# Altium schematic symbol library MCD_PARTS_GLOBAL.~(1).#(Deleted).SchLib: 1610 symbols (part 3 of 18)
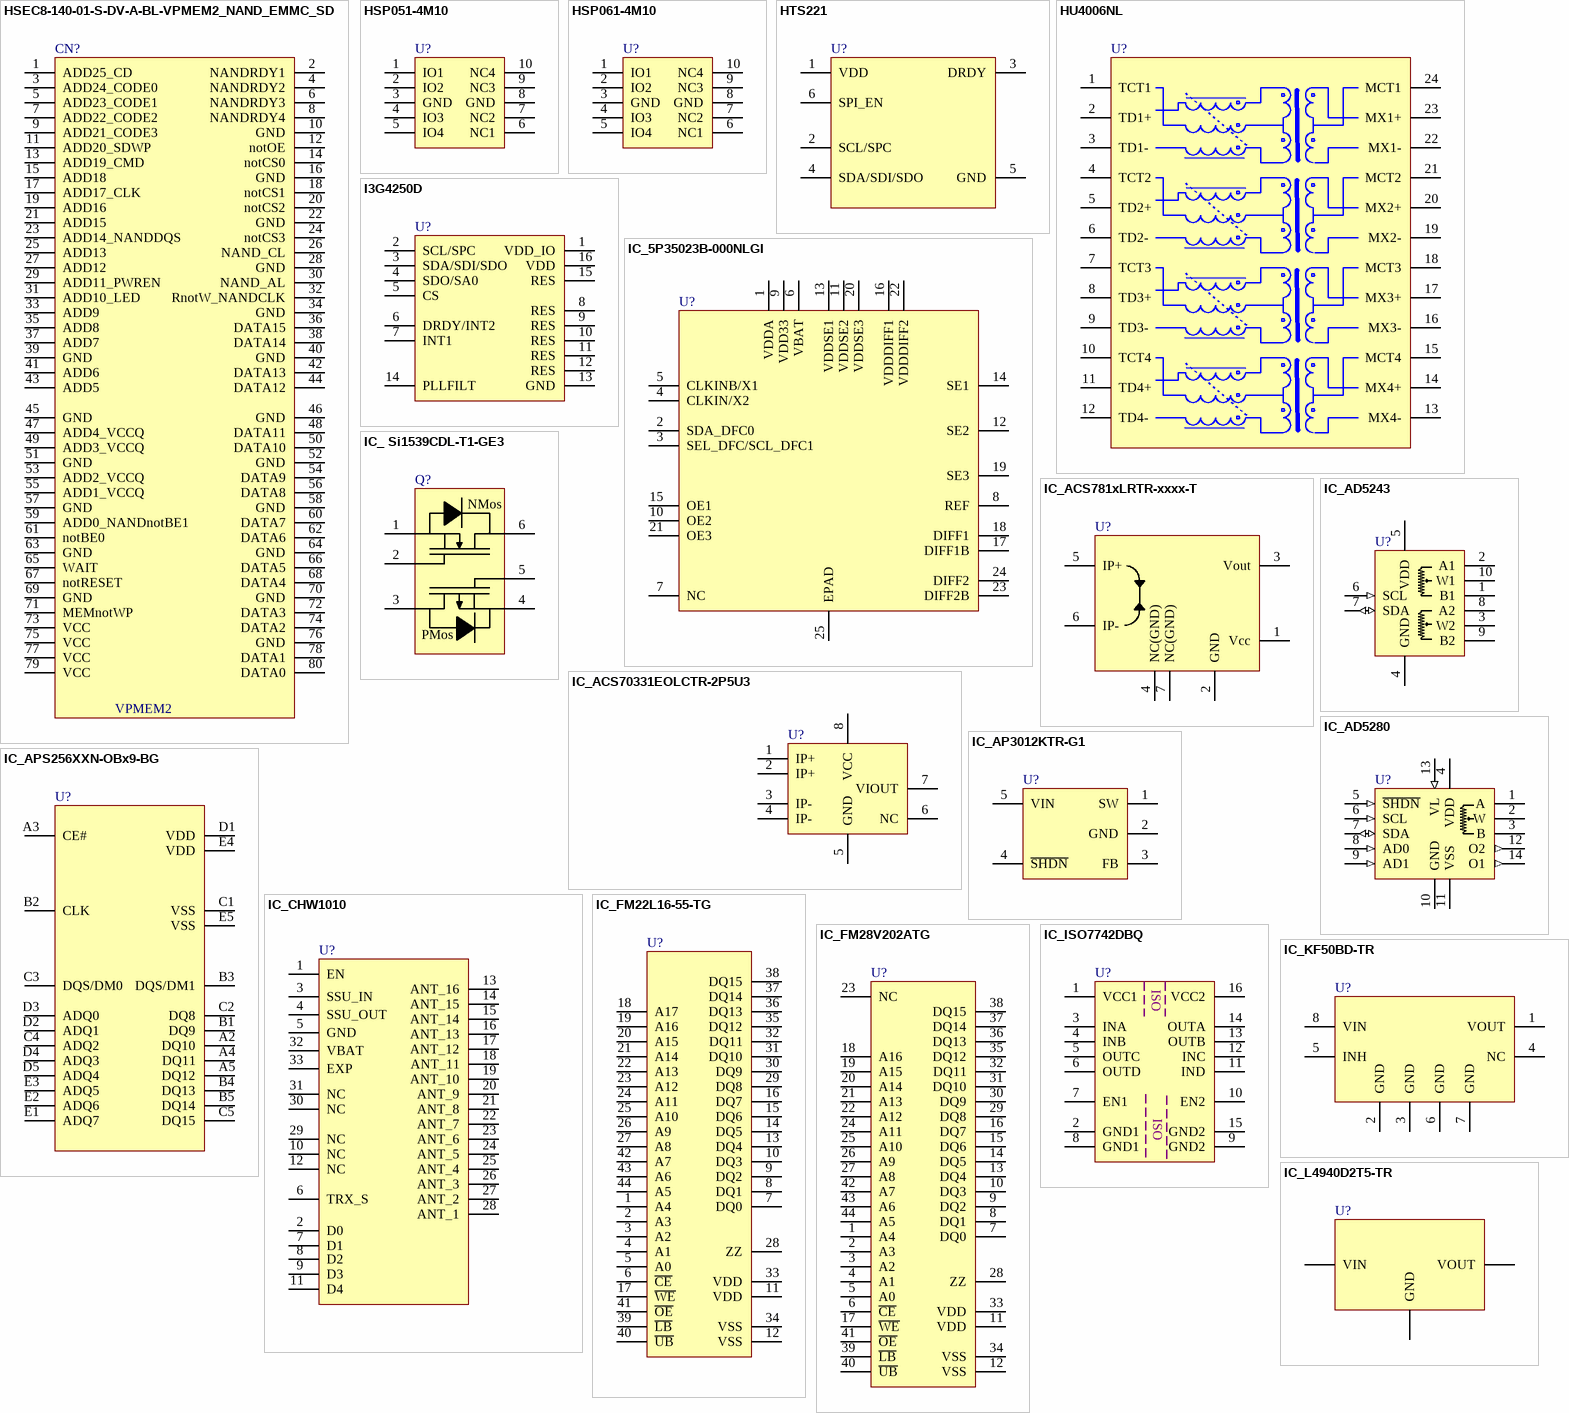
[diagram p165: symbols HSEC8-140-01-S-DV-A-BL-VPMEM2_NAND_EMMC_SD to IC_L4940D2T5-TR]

## HSEC8-140-01-S-DV-A-BL-VPMEM2_NAND_EMMC_SD
designator CN?
pins: 1 ADD25_CD, 2 NANDRDY1, 3 ADD24_CODE0, 4 NANDRDY2, 5 ADD23_CODE1, 6 NANDRDY3, 7 ADD22_CODE2, 8 NANDRDY4, 9 ADD21_CODE3, 10 GND, 11 ADD20_SDWP, 12 notOE, 13 ADD19_CMD, 14 notCS0, 15 ADD18, 16 GND, 17 ADD17_CLK, 18 notCS1, 19 ADD16, 20 notCS2, 21 ADD15, 22 GND, 23 ADD14_NANDDQS, 24 notCS3, 25 ADD13, 26 NAND_CL, 27 ADD12, 28 GND, 29 ADD11_PWREN, 30 NAND_AL, 31 ADD10_LED, 32 RnotW_NANDCLK, 33 ADD9, 34 GND, 35 ADD8, 36 DATA15, 37 ADD7, 38 DATA14, 39 GND, 40 GND, 41 ADD6, 42 DATA13, 43 ADD5, 44 DATA12, 45 GND, 46 GND, 47 ADD4_VCCQ, 48 DATA11, 49 ADD3_VCCQ, 50 DATA10, 51 GND, 52 GND, 53 ADD2_VCCQ, 54 DATA9, 55 ADD1_VCCQ, 56 DATA8, 57 GND, 58 GND, 59 ADD0_NANDnotBE1, 60 DATA7, 61 notBE0, 62 DATA6, 63 GND, 64 GND, 65 WAIT, 66 DATA5, 67 notRESET, 68 DATA4, 69 GND, 70 GND, 71 MEMnotWP, 72 DATA3, 73 VCC, 74 DATA2, 75 VCC, 76 GND, 77 VCC, 78 DATA1, 79 VCC, 80 DATA0

## HSP051-4M10
designator U?
pins: 1 IO1, 2 IO2, 3 GND, 4 IO3, 5 IO4, 6 NC1, 7 NC2, 8 GND, 9 NC3, 10 NC4

## HSP061-4M10
designator U?
pins: 1 IO1, 2 IO2, 3 GND, 4 IO3, 5 IO4, 6 NC1, 7 NC2, 8 GND, 9 NC3, 10 NC4

## HTS221
designator U?
pins: 1 VDD, 2 SCL/SPC, 3 DRDY, 4 SDA/SDI/SDO, 5 GND, 6 SPI_EN

## HU4006NL
designator U?
pins: 1 TCT1, 2 TD1+, 3 TD1-, 4 TCT2, 5 TD2+, 6 TD2-, 7 TCT3, 8 TD3+, 9 TD3-, 10 TCT4, 11 TD4+, 12 TD4-, 13 MX4-, 14 MX4+, 15 MCT4, 16 MX3-, 17 MX3+, 18 MCT3, 19 MX2-, 20 MX2+, 21 MCT2, 22 MX1-, 23 MX1+, 24 MCT1

## I3G4250D
designator U?
pins: 1 VDD_IO, 2 SCL/SPC, 3 SDA/SDI/SDO, 4 SDO/SA0, 5 CS, 6 DRDY/INT2, 7 INT1, 8 RES, 9 RES, 10 RES, 11 RES, 12 RES, 13 GND, 14 PLLFILT, 15 RES, 16 VDD

## IC_5P35023B-000NLGI
designator U?
pins: 1 VDDA, 2 SDA_DFC0, 3 SEL_DFC/SCL_DFC1, 4 CLKIN/X2, 5 CLKINB/X1, 6 VBAT, 7 NC, 8 REF, 9 VDD33, 10 OE2, 11 VDDSE2, 12 SE2, 13 VDDSE1, 14 SE1, 15 OE1, 16 VDDDIFF1, 17 DIFF1B, 18 DIFF1, 19 SE3, 20 VDDSE3, 21 OE3, 22 VDDDIFF2, 23 DIFF2B, 24 DIFF2, 25 EPAD

## IC_ Si1539CDL-T1-GE3
designator Q?
pins: 1 S1, 2 G1, 3 D2, 4 S2, 5 G2, 6 D1

## IC_ACS781xLRTR-xxxx-T
designator U?
pins: 1 Vcc, 2 GND, 3 Vout, 4 NC(GND), 5 IP+, 6 IP-, 7 NC(GND)

## IC_ACS70331EOLCTR-2P5U3
designator U?
pins: 1 IP+, 2 IP+, 3 IP-, 4 IP-, 5 GND, 6 NC, 7 VIOUT, 8 VCC

## IC_AD5243
designator U?
pins: 1 B1, 2 A1, 3 W2, 4 GND, 5 VDD, 6 SCL (in), 7 SDA (io), 8 A2, 9 B2, 10 W1

## IC_AD5280
designator U?
pins: 1 A, 2 W, 3 B, 4 VDD, 5 ~{SHDN} (in), 6 SCL (in), 7 SDA (io), 8 AD0 (in), 9 AD1 (in), 10 GND, 11 VSS, 12 O2 (out), 13 VL (in), 14 O1 (out)

## IC_AP3012KTR-G1
designator U?
pins: 1 SW, 2 GND, 3 FB, 4 ~{SHDN}, 5 VIN

## IC_APS256XXN-OBx9-BG
designator U?
pins: A2 DQ10, A3 CE#, A4 DQ11, A5 DQ12, B1 DQ9, B2 CLK, B3 DQS/DM1, B4 DQ13, B5 DQ14, C1 VSS, C2 DQ8, C3 DQS/DM0, C4 ADQ2, C5 DQ15, D1 VDD, D2 ADQ1, D3 ADQ0, D4 ADQ3, D5 ADQ4, E1 ADQ7, E2 ADQ6, E3 ADQ5, E4 VDD, E5 VSS

## IC_CHW1010
designator U?
pins: 1 EN "CHIP ENABLE", 2 D0 "DIGITAL CONTROL INPUT", 3 SSU_IN "SOFT-SWITCHING RAMP MODULATOR INPUT", 4 SSU_OUT "SOFT-SWITCHING RAMP MODULATOR OUTPUT", 5 GND (power), 6 TRX_S "TRX IN/OUT IN CASE OF SINGLE-END ANTENNA INTERFACE", 7 D1 "DIGITAL CONTROL INPUT", 8 D2 "DIGITAL CONTROL INPUT", 9 D3 "DIGITAL CONTROL INPUT", 10 NC, 11 D4 "DIGITAL CONTROL INPUT", 12 NC, 13 ANT_16 "ANTENNA FEED-PORT 16", 14 ANT_15 "ANTENNA FEED-PORT 15", 15 ANT_14 "ANTENNA FEED-PORT 14", 16 ANT_13 "ANTENNA FEED-PORT 16", 17 ANT_12 "ANTENNA FEED-PORT 12", 18 ANT_11 "ANTENNA FEED-PORT 11", 19 ANT_10 "ANTENNA FEED-PORT 10", 20 ANT_9 "ANTENNA FEED-PORT 9", 21 ANT_8 "ANTENNA FEED-PORT 8", 22 ANT_7 "ANTENNA FEED-PORT 7", 23 ANT_6 "ANTENNA FEED-PORT 6", 24 ANT_5 "ANTENNA FEED-PORT 5", 25 ANT_4 "ANTENNA FEED-PORT 4", 26 ANT_3 "ANTENNA FEED-PORT 3", 27 ANT_2 "ANTENNA FEED-PORT 2", 28 ANT_1 "ANTENNA FEED-PORT 1", 29 NC, 30 NC, 31 NC, 32 VBAT (power) "BATTERY VOLTAGE", 33 EXP (power) "GND"

## IC_FM22L16-55-TG
designator U?
pins: 1 A4, 2 A3, 3 A2, 4 A1, 5 A0, 6 ~{CE}, 7 DQ0, 8 DQ1, 9 DQ2, 10 DQ3, 11 VDD, 12 VSS, 13 DQ4, 14 DQ5, 15 DQ6, 16 DQ7, 17 ~{WE}, 18 A17, 19 A16, 20 A15, 21 A14, 22 A13, 23 A12, 24 A11, 25 A10, 26 A9, 27 A8, 28 ZZ, 29 DQ8, 30 DQ9, 31 DQ10, 32 DQ11, 33 VDD, 34 VSS, 35 DQ12, 36 DQ13, 37 DQ14, 38 DQ15, 39 ~{LB}, 40 ~{UB}, 41 ~{OE}, 42 A7, 43 A6, 44 A5

## IC_FM28V202ATG
designator U?
pins: 1 A4, 2 A3, 3 A2, 4 A1, 5 A0, 6 ~{CE}, 7 DQ0, 8 DQ1, 9 DQ2, 10 DQ3, 11 VDD, 12 VSS, 13 DQ4, 14 DQ5, 15 DQ6, 16 DQ7, 17 ~{WE}, 18 A16, 19 A15, 20 A14, 21 A13, 22 A12, 23 NC, 24 A11, 25 A10, 26 A9, 27 A8, 28 ZZ, 29 DQ8, 30 DQ9, 31 DQ10, 32 DQ11, 33 VDD, 34 VSS, 35 DQ12, 36 DQ13, 37 DQ14, 38 DQ15, 39 ~{LB}, 40 ~{UB}, 41 ~{OE}, 42 A7, 43 A6, 44 A5

## IC_ISO7742DBQ
designator U?
pins: 1 VCC1 (power), 2 GND1 (power), 3 INA, 4 INB, 5 OUTC, 6 OUTD, 7 EN1, 8 GND1 (power), 9 GND2 (power), 10 EN2, 11 IND, 12 INC, 13 OUTB, 14 OUTA, 15 GND2 (power), 16 VCC2 (power)

## IC_KF50BD-TR
designator U?
pins: 1 VOUT, 2 GND, 3 GND, 4 NC, 5 INH, 6 GND, 7 GND, 8 VIN

## IC_L4940D2T5-TR
designator U?
pins: 1 VIN (power), 2 GND (power), 3 VOUT (power)

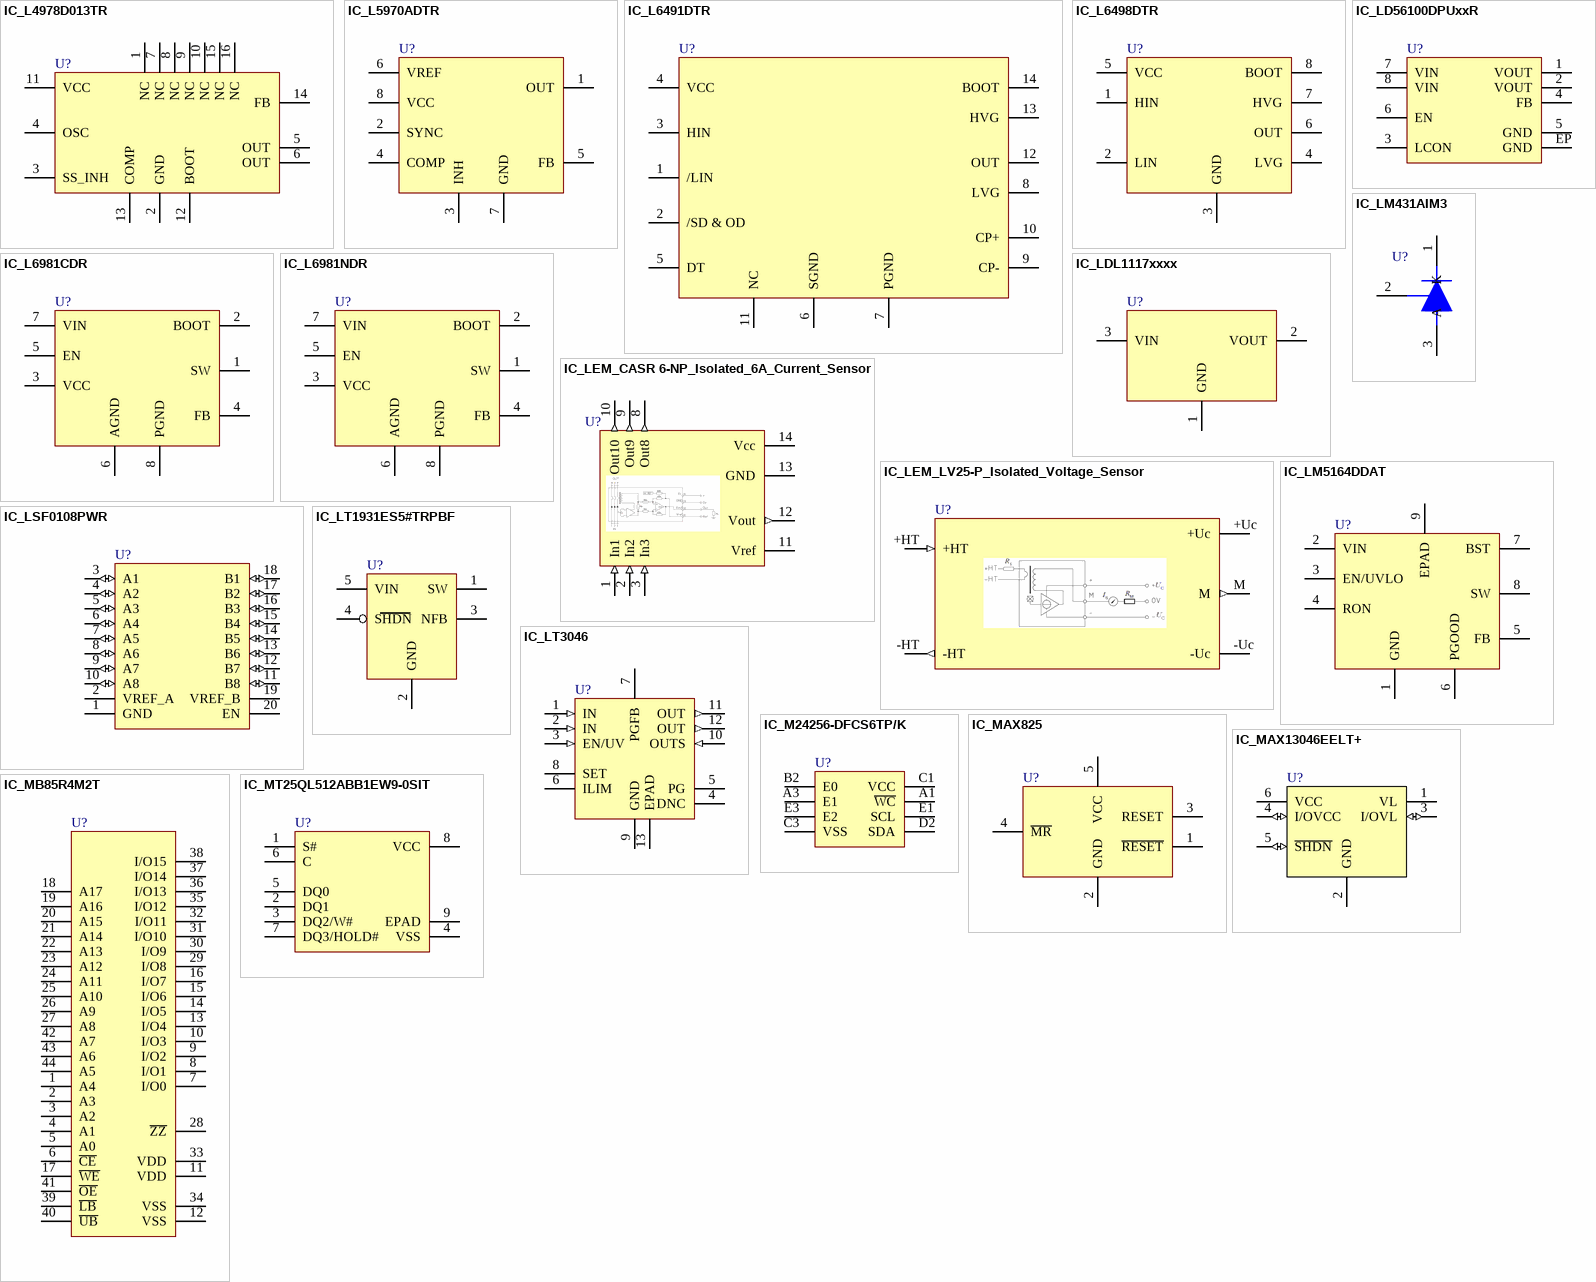
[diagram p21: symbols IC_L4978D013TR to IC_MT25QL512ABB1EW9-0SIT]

## IC_L4978D013TR
designator U?
pins: 1 NC, 2 GND (power), 3 SS_INH, 4 OSC, 5 OUT, 6 OUT, 7 NC, 8 NC, 9 NC, 10 NC, 11 VCC (power), 12 BOOT, 13 COMP, 14 FB, 15 NC, 16 NC

## IC_L5970ADTR
designator U?
pins: 1 OUT, 2 SYNC, 3 INH, 4 COMP, 5 FB, 6 VREF, 7 GND, 8 VCC (power)

## IC_L6491DTR
designator U?
pins: 1 /LIN, 2 /SD & OD, 3 HIN, 4 VCC (power), 5 DT, 6 SGND, 7 PGND, 8 LVG, 9 CP-, 10 CP+, 11 NC, 12 OUT, 13 HVG, 14 BOOT

## IC_L6498DTR
designator U?
pins: 1 HIN, 2 LIN, 3 GND, 4 LVG, 5 VCC (power), 6 OUT, 7 HVG, 8 BOOT

## IC_L6981CDR
designator U?
pins: 1 SW, 2 BOOT, 3 VCC, 4 FB, 5 EN (power), 6 AGND, 7 VIN, 8 PGND

## IC_L6981NDR
designator U?
pins: 1 SW, 2 BOOT, 3 VCC, 4 FB, 5 EN (power), 6 AGND, 7 VIN, 8 PGND

## IC_LD56100DPUxxR
designator U?
pins: 1 VOUT, 2 VOUT, 3 LCON, 4 FB, 5 GND, 6 EN, 7 VIN, 8 VIN, EP GND

## IC_LDL1117xxxx
designator U?
pins: 1 GND, 2 VOUT, 3 VIN

## IC_LEM_CASR 6-NP_Isolated_6A_Current_Sensor
designator U?
pins: 1 In1 (in), 2 In2 (in), 3 In3 (in), 8 Out8 (out), 9 Out9 (out), 10 Out10 (out), 11 Vref (power), 12 Vout (out), 13 GND (power), 14 Vcc (power)

## IC_LEM_LV25-P_Isolated_Voltage_Sensor
designator U?
pins: +HT (in), +Uc (power), -HT (out), -Uc (power), M (out)

## IC_LM431AIM3
designator U?
pins: 1 K, 2 Ref, 3 A

## IC_LM5164DDAT
designator U?
pins: 1 GND, 2 VIN, 3 EN/UVLO (power), 4 RON, 5 FB, 6 PGOOD, 7 BST, 8 SW, 9 EPAD

## IC_LSF0108PWR
designator U?
pins: 1 GND (power), 2 VREF_A (power), 3 A1 (io), 4 A2 (io), 5 A3 (io), 6 A4 (io), 7 A5 (io), 8 A6 (io), 9 A7 (io), 10 A8 (io), 11 B8 (io), 12 B7 (io), 13 B6 (io), 14 B5 (io), 15 B4 (io), 16 B3 (io), 17 B2 (io), 18 B1 (io), 19 VREF_B (power), 20 EN (power)

## IC_LT1931ES5#TRPBF
designator U?
pins: 1 SW, 2 GND, 3 NFB, 4 SHDN (power), 5 VIN

## IC_LT3046
designator U?
pins: 1 IN (in), 2 IN (in), 3 EN/UV (in), 4 DNC, 5 PG (oc), 6 ILIM, 7 PGFB, 8 SET, 9 GND, 10 OUTS (in), 11 OUT (out), 12 OUT (out), 13 EPAD

## IC_M24256-DFCS6TP/K
designator U?
pins: A1 ~{WC}, A3 E1, B2 E0, C1 VCC, C3 VSS, D2 SDA, E1 SCL, E3 E2

## IC_MAX825
designator U?
pins: 1 ~{RESET}, 2 GND, 3 RESET, 4 ~{MR}, 5 VCC

## IC_MAX13046EELT+
designator U?
pins: 1 VL (power), 2 GND (power), 3 I/OVL (io), 4 I/OVCC (io), 5 ~{SHDN} (io), 6 VCC (power)

## IC_MB85R4M2T
designator U?
pins: 1 A4, 2 A3, 3 A2, 4 A1, 5 A0, 6 ~{CE}, 7 I/O0, 8 I/O1, 9 I/O2, 10 I/O3, 11 VDD, 12 VSS, 13 I/O4, 14 I/O5, 15 I/O6, 16 I/O7, 17 ~{WE}, 18 A17, 19 A16, 20 A15, 21 A14, 22 A13, 23 A12, 24 A11, 25 A10, 26 A9, 27 A8, 28 ~{ZZ}, 29 I/O8, 30 I/O9, 31 I/O10, 32 I/O11, 33 VDD, 34 VSS, 35 I/O12, 36 I/O13, 37 I/O14, 38 I/O15, 39 ~{LB}, 40 ~{UB}, 41 ~{OE}, 42 A7, 43 A6, 44 A5

## IC_MT25QL512ABB1EW9-0SIT
designator U?
pins: 1 S#, 2 DQ1, 3 DQ2/W#, 4 VSS, 5 DQ0, 6 C, 7 DQ3/HOLD#, 8 VCC, 9 EPAD

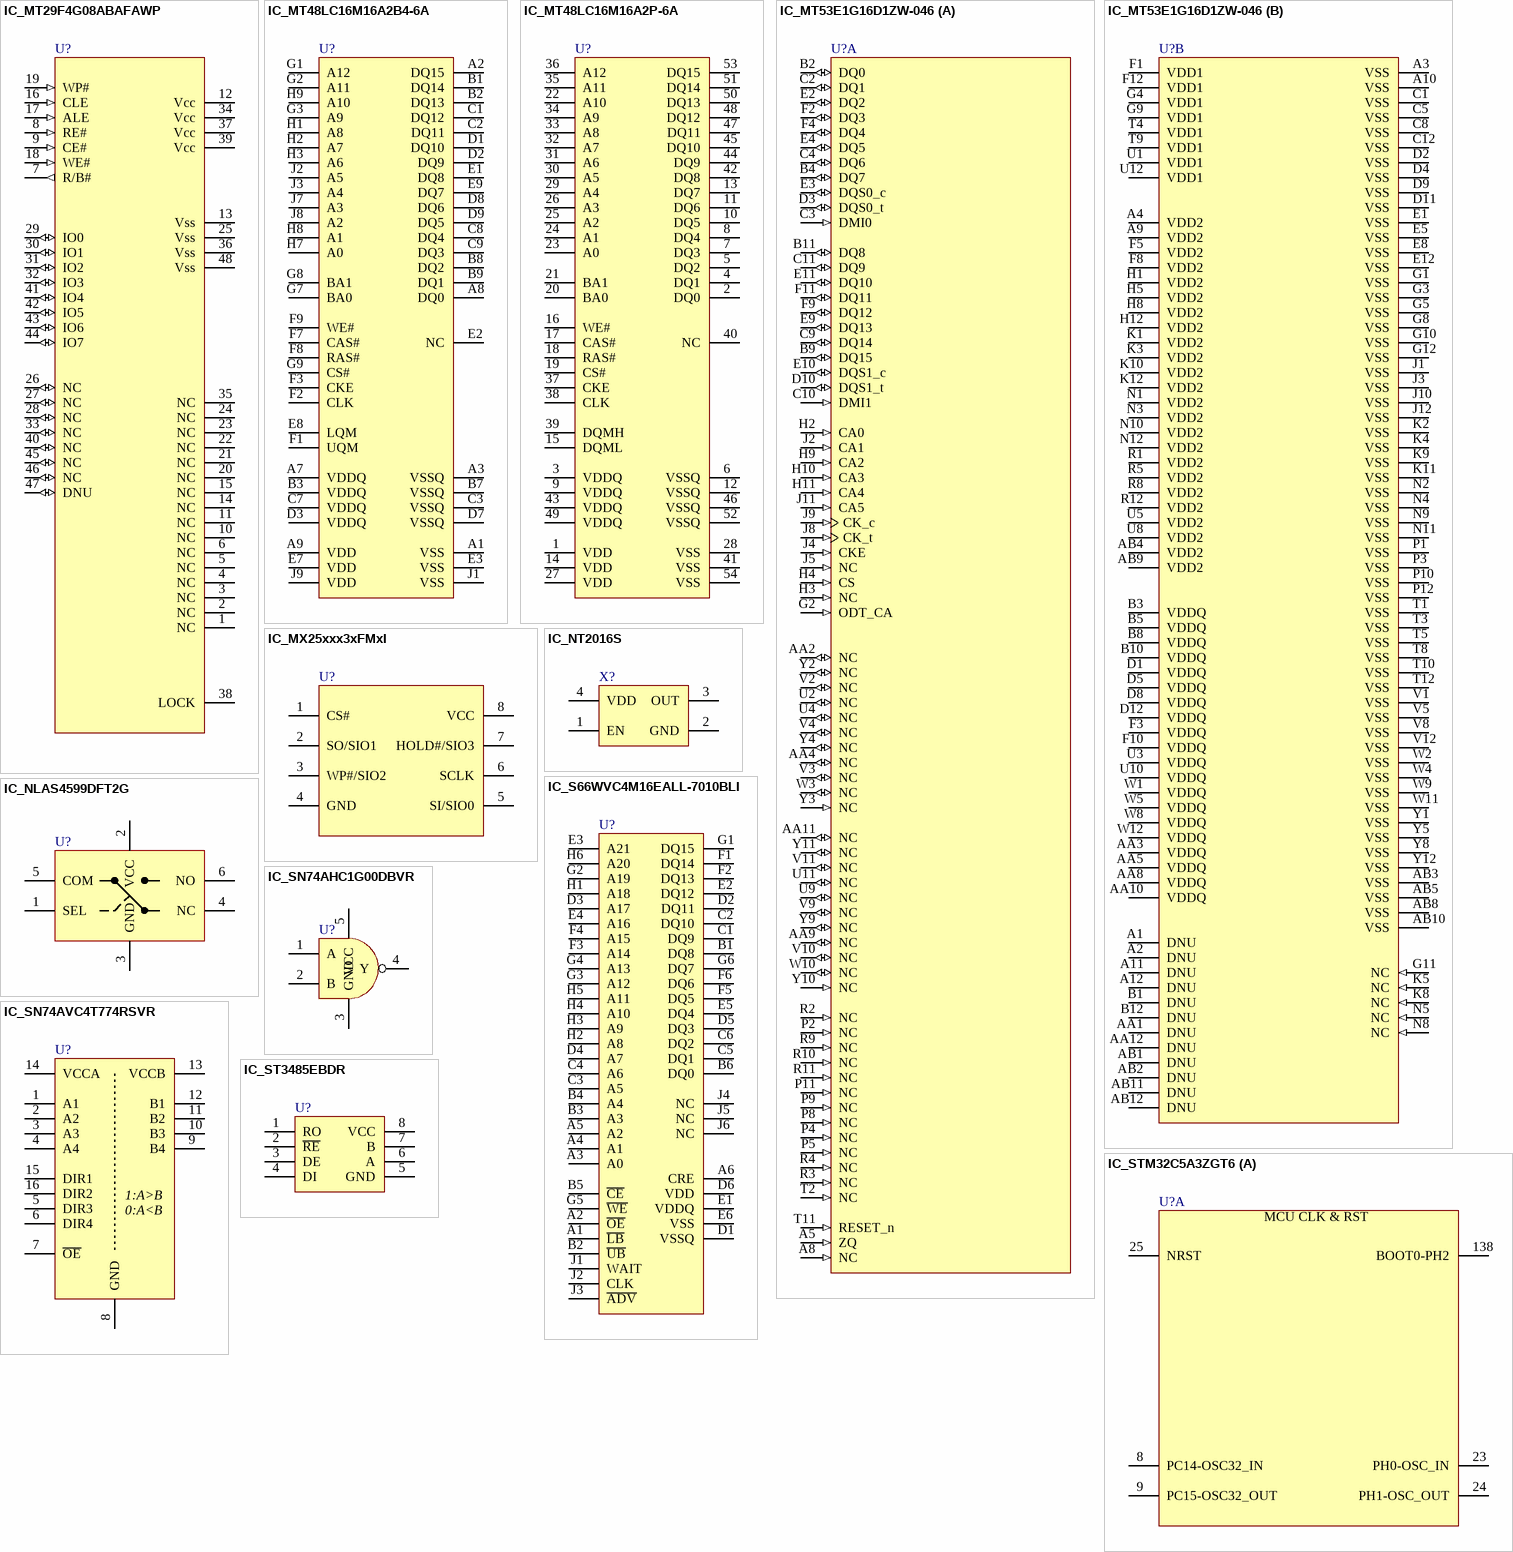
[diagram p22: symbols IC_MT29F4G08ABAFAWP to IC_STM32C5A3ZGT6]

## IC_MT29F4G08ABAFAWP
designator U?
pins: 1 NC, 2 NC, 3 NC, 4 NC, 5 NC, 6 NC, 7 R/B# (out), 8 RE# (in), 9 CE# (in), 10 NC, 11 NC, 12 Vcc (power), 13 Vss (power), 14 NC, 15 NC, 16 CLE (in), 17 ALE (in), 18 WE# (in), 19 WP# (in), 20 NC, 21 NC, 22 NC, 23 NC, 24 NC, 25 Vss (power), 26 NC (io), 27 NC (io), 28 NC (io), 29 IO0 (io), 30 IO1 (io), 31 IO2 (io), 32 IO3 (io), 33 NC (io), 34 Vcc (power), 35 NC, 36 Vss (power), 37 Vcc (power), 38 LOCK, 39 Vcc (power), 40 NC (io), 41 IO4 (io), 42 IO5 (io), 43 IO6 (io), 44 IO7 (io), 45 NC (io), 46 NC (io), 47 DNU (io), 48 Vss (power)

## IC_MT48LC16M16A2B4-6A
designator U?
pins: A1 VSS, A2 DQ15, A3 VSSQ, A7 VDDQ, A8 DQ0, A9 VDD, B1 DQ14, B2 DQ13, B3 VDDQ, B7 VSSQ, B8 DQ2, B9 DQ1, C1 DQ12, C2 DQ11, C3 VSSQ, C7 VDDQ, C8 DQ4, C9 DQ3, D1 DQ10, D2 DQ9, D3 VDDQ, D7 VSSQ, D8 DQ6, D9 DQ5, E1 DQ8, E2 NC, E3 VSS, E7 VDD, E8 LQM, E9 DQ7, F1 UQM, F2 CLK, F3 CKE, F7 CAS#, F8 RAS#, F9 WE#, G1 A12, G2 A11, G3 A9, G7 BA0, G8 BA1, G9 CS#, H1 A8, H2 A7, H3 A6, H7 A0, H8 A1, H9 A10, J1 VSS, J2 A5, J3 A4, J7 A3, J8 A2, J9 VDD

## IC_MT48LC16M16A2P-6A
designator U?
pins: 1 VDD, 2 DQ0, 3 VDDQ, 4 DQ1, 5 DQ2, 6 VSSQ, 7 DQ3, 8 DQ4, 9 VDDQ, 10 DQ5, 11 DQ6, 12 VSSQ, 13 DQ7, 14 VDD, 15 DQML, 16 WE#, 17 CAS#, 18 RAS#, 19 CS#, 20 BA0, 21 BA1, 22 A10, 23 A0, 24 A1, 25 A2, 26 A3, 27 VDD, 28 VSS, 29 A4, 30 A5, 31 A6, 32 A7, 33 A8, 34 A9, 35 A11, 36 A12, 37 CKE, 38 CLK, 39 DQMH, 40 NC, 41 VSS, 42 DQ8, 43 VDDQ, 44 DQ9, 45 DQ10, 46 VSSQ, 47 DQ11, 48 DQ12, 49 VDDQ, 50 DQ13, 51 DQ14, 52 VSSQ, 53 DQ15, 54 VSS

## IC_MT53E1G16D1ZW-046
designator U?
part A pins: A5 ZQ (in) "External impedance (240 ohm): This signal is used to calibrate the device output impedance.", A8 NC (in), AA2 NC (io) "Data input/output: Bidirectional data bus.", AA4 NC (io) "Data input/output: Bidirectional data bus.", AA9 NC (io) "Data input/output: Bidirectional data bus.", AA11 NC (io) "Data input/output: Bidirectional data bus.", B2 DQ0 (io) "Data input/output: Bidirectional data bus.", B4 DQ7 (io) "Data input/output: Bidirectional data bus.", B9 DQ15 (io) "Data input/output: Bidirectional data bus.", B11 DQ8 (io) "Data input/output: Bidirectional data bus.", C2 DQ1 (io) "Data input/output: Bidirectional data bus.", C3 DMI0 (in) "Input data mask: DM is an input mask signal for write data. Although DM ballsare input-only, the DM loading is designed to match that of DQ and DQS balls.DM[3:0] is DM for each of the four data bytes, respectively.", C4 DQ6 (io) "Data input/output: Bidirectional data bus.", C9 DQ14 (io) "Data input/output: Bidirectional data bus.", C10 DMI1 (in) "Input data mask: DM is an input mask signal for write data. Although DM ballsare input-only, the DM loading is designed to match that of DQ and DQS balls.DM[3:0] is DM for each of the four data bytes, respectively.", C11 DQ9 (io) "Data input/output: Bidirectional data bus.", D3 DQS0_t (io) "Data strobe: The data strobe is bidirectional (used for read and write data) andcomplementary (DQS and DQS#). It is edge-aligned output with read data andcentered input with write data. DQS[3:0]/DQS[3:0]# is DQS for each of (See Datasheet)", D10 DQS1_t (io) "Data strobe: The data strobe is bidirectional (used for read and write data) andcomplementary (DQS and DQS#). It is edge-aligned output with read data andcentered input with write data. DQS[3:0]/DQS[3:0]# is DQS for each of (See Datasheet)", E2 DQ2 (io) "Data input/output: Bidirectional data bus.", E3 DQS0_c (io) "Data strobe: The data strobe is bidirectional (used for read and write data) andcomplementary (DQS and DQS#). It is edge-aligned output with read data andcentered input with write data. DQS[3:0]/DQS[3:0]# is DQS for each of (See Datasheet)", E4 DQ5 (io) "Data input/output: Bidirectional data bus.", E9 DQ13 (io) "Data input/output: Bidirectional data bus.", E10 DQS1_c (io) "Data strobe: The data strobe is bidirectional (used for read and write data) andcomplementary (DQS and DQS#). It is edge-aligned output with read data andcentered input with write data. DQS[3:0]/DQS[3:0]# is DQS for each of (See Datasheet)", E11 DQ10 (io) "Data input/output: Bidirectional data bus.", F2 DQ3 (io) "Data input/output: Bidirectional data bus.", F4 DQ4 (io) "Data input/output: Bidirectional data bus.", F9 DQ12 (io) "Data input/output: Bidirectional data bus.", F11 DQ11 (io) "Data input/output: Bidirectional data bus.", G2 ODT_CA (in) "on die termination on CA", H2 CA0 (in) "Command/address inputs: Provide the command and address inputs accordingto the command truth table.", H3 NC (in), H4 CS (in) "Chip select: CS# is considered part of the command code and is sampled at therising edge of CK.", H9 CA2 (in) "Command/address inputs: Provide the command and address inputs accordingto the command truth table.", H10 CA3 (in) "Command/address inputs: Provide the command and address inputs accordingto the command truth table.", H11 CA4 (in) "Command/address inputs: Provide the command and address inputs accordingto the command truth table.", J2 CA1 (in) "Command/address inputs: Provide the command and address inputs accordingto the command truth table.", J4 CKE (in) "Clock enable: CKE HIGH activates and CKE LOW deactivates the internal clocksignals, input buffers, and output drivers. Power-saving modes are entered andexited via CKE transitions. CKE is considered part of the command code. (See Datasheet)", J5 NC (in), J8 CK_t (in) "Clock: CK and CK# are differential clock inputs. All CA inputs are sampled onboth rising and falling edges of CK. CS and CKE inputs are sampled at the risingedge of CK. AC timings are referenced to clock.", J9 CK_c (in) "Clock: CK and CK# are differential clock inputs. All CA inputs are sampled onboth rising and falling edges of CK. CS and CKE inputs are sampled at the risingedge of CK. AC timings are referenced to clock.", J11 CA5 (in) "Command/address inputs: Provide the command and address inputs accordingto the command truth table.", P2 NC (in) "Command/address inputs: Provide the command and address inputs accordingto the command truth table.", P4 NC (in) "Clock enable: CKE HIGH activates and CKE LOW deactivates the internal clocksignals, input buffers, and output drivers. Power-saving modes are entered andexited via CKE transitions. CKE is considered part of the command code. (See Datasheet)", P5 NC (in), P8 NC (in) "Clock: CK and CK# are differential clock inputs. All CA inputs are sampled onboth rising and falling edges of CK. CS and CKE inputs are sampled at the risingedge of CK. AC timings are referenced to clock.", P9 NC (in) "Clock: CK and CK# are differential clock inputs. All CA inputs are sampled onboth rising and falling edges of CK. CS and CKE inputs are sampled at the risingedge of CK. AC timings are referenced to clock.", P11 NC (in) "Command/address inputs: Provide the command and address inputs accordingto the command truth table.", R2 NC (in) "Command/address inputs: Provide the command and address inputs accordingto the command truth table.", R3 NC (in), R4 NC (in) "Chip select: CS# is considered part of the command code and is sampled at therising edge of CK.", R9 NC (in) "Command/address inputs: Provide the command and address inputs accordingto the command truth table.", R10 NC (in) "Command/address inputs: Provide the command and address inputs accordingto the command truth table.", R11 NC (in) "Command/address inputs: Provide the command and address inputs accordingto the command truth table.", T2 NC (in) "on die termination on CA", T11 RESET_n (in) "Reset active low", U2 NC (io) "Data input/output: Bidirectional data bus.", U4 NC (io) "Data input/output: Bidirectional data bus.", U9 NC (io) "Data input/output: Bidirectional data bus.", U11 NC (io) "Data input/output: Bidirectional data bus.", V2 NC (io) "Data input/output: Bidirectional data bus.", V3 NC (io) "Data strobe: The data strobe is bidirectional (used for read and write data) andcomplementary (DQS and DQS#). It is edge-aligned output with read data andcentered input with write data. DQS[3:0]/DQS[3:0]# is DQS for each of (See Datasheet)", V4 NC (io) "Data input/output: Bidirectional data bus.", V9 NC (io) "Data input/output: Bidirectional data bus.", V10 NC (io) "Data strobe: The data strobe is bidirectional (used for read and write data) andcomplementary (DQS and DQS#). It is edge-aligned output with read data andcentered input with write data. DQS[3:0]/DQS[3:0]# is DQS for each of (See Datasheet)", V11 NC (io) "Data input/output: Bidirectional data bus.", W3 NC (io) "Data strobe: The data strobe is bidirectional (used for read and write data) andcomplementary (DQS and DQS#). It is edge-aligned output with read data andcentered input with write data. DQS[3:0]/DQS[3:0]# is DQS for each of (See Datasheet)", W10 NC (io) "Data strobe: The data strobe is bidirectional (used for read and write data) andcomplementary (DQS and DQS#). It is edge-aligned output with read data andcentered input with write data. DQS[3:0]/DQS[3:0]# is DQS for each of (See Datasheet)", Y2 NC (io) "Data input/output: Bidirectional data bus.", Y3 NC (in) "Input data mask: DM is an input mask signal for write data. Although DM ballsare input-only, the DM loading is designed to match that of DQ and DQS balls.DM[3:0] is DM for each of the four data bytes, respectively.", Y4 NC (io) "Data input/output: Bidirectional data bus.", Y9 NC (io) "Data input/output: Bidirectional data bus.", Y10 NC (in) "Input data mask: DM is an input mask signal for write data. Although DM ballsare input-only, the DM loading is designed to match that of DQ and DQS balls.DM[3:0] is DM for each of the four data bytes, respectively.", Y11 NC (io) "Data input/output: Bidirectional data bus."
part B pins: A1 DNU "Do not use: Must be grounded or left floating.", A2 DNU "Do not use: Must be grounded or left floating.", A3 VSS (power) "Common ground.", A4 VDD2 (power) "Core power: Supply 2.", A9 VDD2 (power) "Core power: Supply 2.", A10 VSS (power) "Common ground.", A11 DNU "Do not use: Must be grounded or left floating.", A12 DNU "Do not use: Must be grounded or left floating.", AA1 DNU "Do not use: Must be grounded or left floating.", AA3 VDDQ (power) "DQ power supply: Isolated on the die for improved noise immunity.", AA5 VDDQ (power) "DQ power supply: Isolated on the die for improved noise immunity.", AA8 VDDQ (power) "DQ power supply: Isolated on the die for improved noise immunity.", AA10 VDDQ (power) "DQ power supply: Isolated on the die for improved noise immunity.", AA12 DNU "Do not use: Must be grounded or left floating.", AB1 DNU "Do not use: Must be grounded or left floating.", AB2 DNU "Do not use: Must be grounded or left floating.", AB3 VSS "Common ground.", AB4 VDD2 (power) "Core power: Supply 2.", AB5 VSS "Common ground.", AB8 VSS "Common ground.", AB9 VDD2 (power) "Core power: Supply 2.", AB10 VSS "Common ground.", AB11 DNU "Do not use: Must be grounded or left floating.", AB12 DNU "Do not use: Must be grounded or left floating.", B1 DNU "Do not use: Must be grounded or left floating.", B3 VDDQ (power) "DQ power supply: Isolated on the die for improved noise immunity.", B5 VDDQ (power) "DQ power supply: Isolated on the die for improved noise immunity.", B8 VDDQ (power) "DQ power supply: Isolated on the die for improved noise immunity.", B10 VDDQ (power) "DQ power supply: Isolated on the die for improved noise immunity.", B12 DNU "Do not use: Must be grounded or left floating.", C1 VSS (power) "Common ground.", C5 VSS (power) "Common ground.", C8 VSS (power) "Common ground.", C12 VSS (power) "Common ground.", D1 VDDQ (power) "DQ power supply: Isolated on the die for improved noise immunity.", D2 VSS (power) "Common ground.", D4 VSS (power) "Common ground.", D5 VDDQ (power) "DQ power supply: Isolated on the die for improved noise immunity.", D8 VDDQ (power) "DQ power supply: Isolated on the die for improved noise immunity.", D9 VSS (power) "Common ground.", D11 VSS (power) "Common ground.", D12 VDDQ (power) "DQ power supply: Isolated on the die for improved noise immunity.", E1 VSS (power) "Common ground.", E5 VSS (power) "Common ground.", E8 VSS (power) "Common ground.", E12 VSS (power) "Common ground.", F1 VDD1 (power) "Core power: Supply 1.", F3 VDDQ (power) "DQ power supply: Isolated on the die for improved noise immunity.", F5 VDD2 (power) "Core power: Supply 2.", F8 VDD2 (power) "Core power: Supply 2.", F10 VDDQ (power) "DQ power supply: Isolated on the die for improved noise immunity.", F12 VDD1 (power) "Core power: Supply 1.", G1 VSS (power) "Common ground.", G3 VSS (power) "Common ground.", G4 VDD1 (power) "Core power: Supply 1.", G5 VSS (power) "Common ground.", G8 VSS (power) "Common ground.", G9 VDD1 (power) "Core power: Supply 1.", G10 VSS (power) "Common ground.", G11 NC (in) "Not connected", G12 VSS (power) "Common ground.", H1 VDD2 (power) "Core power: Supply 2.", H5 VDD2 (power) "Core power: Supply 2.", H8 VDD2 (power) "Core power: Supply 2.", H12 VDD2 (power) "Core power: Supply 2.", J1 VSS (power) "Common ground.", J3 VSS (power) "Common ground.", J10 VSS (power) "Common ground.", J12 VSS (power) "Common ground.", K1 VDD2 (power) "Core power: Supply 2.", K2 VSS (power) "Common ground.", K3 VDD2 (power) "Core power: Supply 2.", K4 VSS (power) "Common ground.", K5 NC (in) "Not connected", K8 NC (in) "Not connected", K9 VSS (power) "Common ground.", K10 VDD2 (power) "Core power: Supply 2.", K11 VSS "Common ground.", K12 VDD2 (power) "Core power: Supply 2.", N1 VDD2 (power) "Core power: Supply 2.", N2 VSS "Common ground.", N3 VDD2 (power) "Core power: Supply 2.", N4 VSS "Common ground.", N5 NC (in) "Not connected", N8 NC (in) "Not connected", N9 VSS "Common ground.", N10 VDD2 (power) "Core power: Supply 2.", N11 VSS "Common ground.", N12 VDD2 (power) "Core power: Supply 2.", P1 VSS "Common ground.", P3 VSS (power) "Common ground.", P10 VSS (power) "Common ground.", P12 VSS "Common ground.", R1 VDD2 (power) "Core power: Supply 2.", R5 VDD2 (power) "Core power: Supply 2.", R8 VDD2 (power) "Core power: Supply 2.", R12 VDD2 (power) "Core power: Supply 2.", T1 VSS "Common ground.", T3 VSS "Common ground.", T4 VDD1 (power) "Core power: Supply 1.", T5 VSS "Common ground.", T8 VSS "Common ground.", T9 VDD1 (power) "Core power: Supply 1.", T10 VSS "Common ground.", T12 VSS "Common ground.", U1 VDD1 (power) "Core power: Supply 1.", U3 VDDQ (power) "DQ power supply: Isolated on the die for improved noise immunity.", U5 VDD2 (power) "Core power: Supply 2.", U8 VDD2 (power) "Core power: Supply 2.", U10 VDDQ (power) "DQ power supply: Isolated on the die for improved noise immunity.", U12 VDD1 (power) "Core power: Supply 1.", V1 VSS (power) "Common ground.", V5 VSS (power) "Common ground.", V8 VSS "Common ground.", V12 VSS "Common ground.", W1 VDDQ (power) "DQ power supply: Isolated on the die for improved noise immunity.", W2 VSS "Common ground.", W4 VSS "Common ground.", W5 VDDQ (power) "DQ power supply: Isolated on the die for improved noise immunity.", W8 VDDQ (power) "DQ power supply: Isolated on the die for improved noise immunity.", W9 VSS "Common ground.", W11 VSS "Common ground.", W12 VDDQ (power) "DQ power supply: Isolated on the die for improved noise immunity.", Y1 VSS "Common ground.", Y5 VSS "Common ground.", Y8 VSS "Common ground.", Y12 VSS "Common ground."

## IC_MX25xxx3xFMxI
designator U?
pins: 1 CS#, 2 SO/SIO1, 3 WP#/SIO2, 4 GND, 5 SI/SIO0, 6 SCLK, 7 HOLD#/SIO3, 8 VCC

## IC_NLAS4599DFT2G
designator U?
pins: 1 SEL, 2 VCC, 3 GND, 4 NC, 5 COM, 6 NO

## IC_NT2016S
designator X?
pins: 1 EN, 2 GND, 3 OUT, 4 VDD

## IC_S66WVC4M16EALL-7010BLI
designator U?
pins: A1 ~{LB}, A2 ~{OE}, A3 A0, A4 A1, A5 A2, A6 CRE, B1 DQ8, B2 ~{UB}, B3 A3, B4 A4, B5 ~{CE}, B6 DQ0, C1 DQ9, C2 DQ10, C3 A5, C4 A6, C5 DQ1, C6 DQ2, D1 VSSQ, D2 DQ11, D3 A17, D4 A7, D5 DQ3, D6 VDD, E1 VDDQ, E2 DQ12, E3 A21, E4 A16, E5 DQ4, E6 VSS, F1 DQ14, F2 DQ13, F3 A14, F4 A15, F5 DQ5, F6 DQ6, G1 DQ15, G2 A19, G3 A12, G4 A13, G5 ~{WE}, G6 DQ7, H1 A18, H2 A8, H3 A9, H4 A10, H5 A11, H6 A20, J1 WAIT, J2 CLK, J3 ~{ADV}, J4 NC, J5 NC, J6 NC

## IC_SN74AHC1G00DBVR
designator U?
pins: 1 NC hidden, 1 A, 2 B, 3 GND, 4 Y, 5 VCC

## IC_SN74AVC4T774RSVR
designator U?
pins: 1 A1, 2 A2, 3 A3, 4 A4, 5 DIR3, 6 DIR4, 7 ~{OE}, 8 GND, 9 B4, 10 B3, 11 B2, 12 B1, 13 VCCB, 14 VCCA, 15 DIR1, 16 DIR2

## IC_ST3485EBDR
designator U?
pins: 1 RO, 2 ~{RE}, 3 DE, 4 DI, 5 GND, 6 A, 7 B, 8 VCC

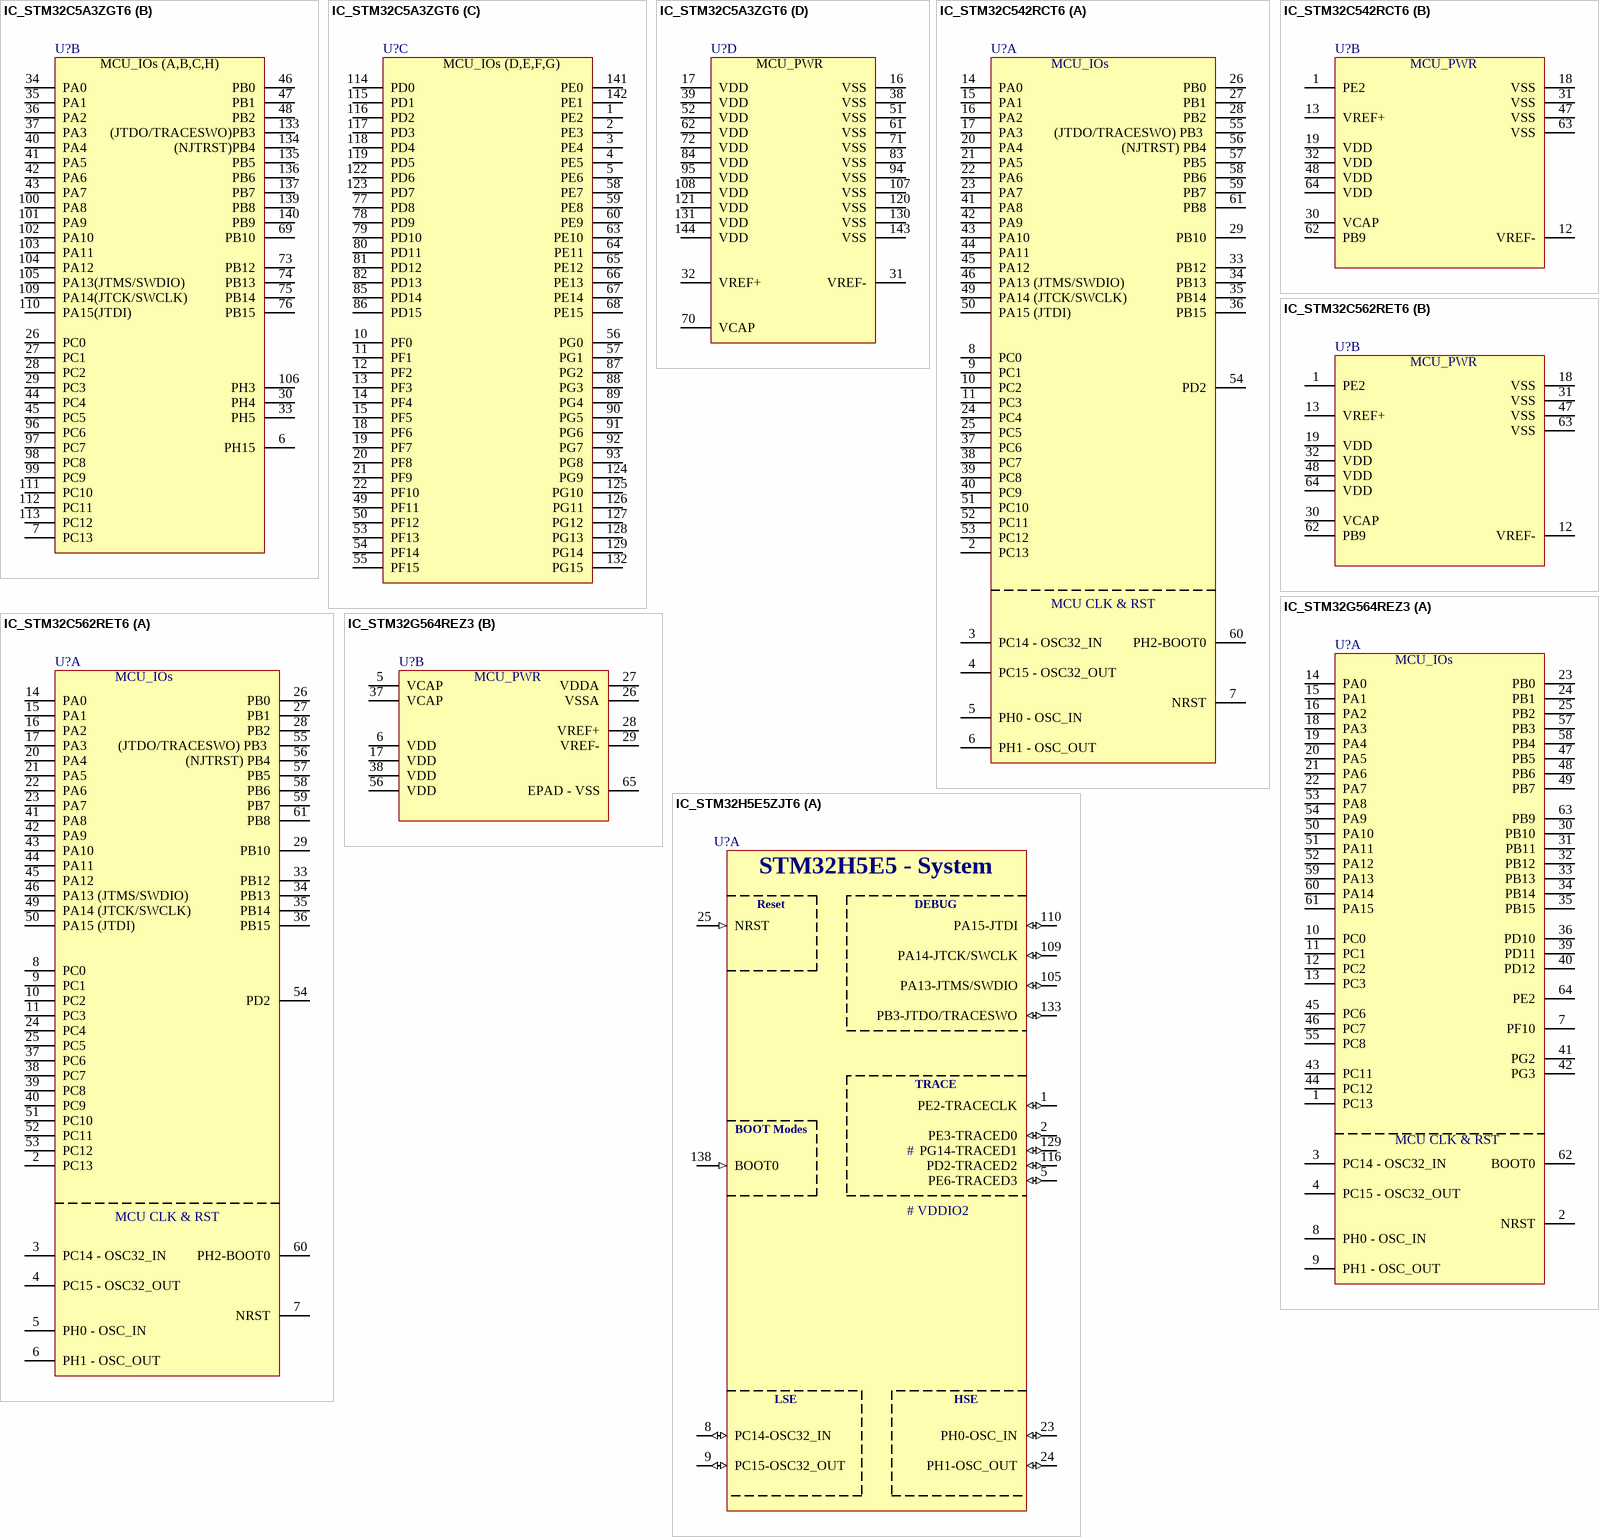
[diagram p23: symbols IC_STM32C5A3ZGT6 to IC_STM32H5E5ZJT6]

## IC_STM32C5A3ZGT6
designator U?
part A pins: 8 PC14-OSC32_IN, 9 PC15-OSC32_OUT, 23 PH0-OSC_IN, 24 PH1-OSC_OUT, 25 NRST, 138 BOOT0-PH2
part B pins: 6 PH15, 7 PC13, 26 PC0, 27 PC1, 28 PC2, 29 PC3, 30 PH4, 33 PH5, 34 PA0, 35 PA1, 36 PA2, 37 PA3, 40 PA4, 41 PA5, 42 PA6, 43 PA7, 44 PC4, 45 PC5, 46 PB0, 47 PB1, 48 PB2, 69 PB10, 73 PB12, 74 PB13, 75 PB14, 76 PB15, 96 PC6, 97 PC7, 98 PC8, 99 PC9, 100 PA8, 101 PA9, 102 PA10, 103 PA11, 104 PA12, 105 PA13(JTMS/SWDIO), 106 PH3, 109 PA14(JTCK/SWCLK), 110 PA15(JTDI), 111 PC10, 112 PC11, 113 PC12, 133 (JTDO/TRACESWO)PB3, 134 (NJTRST)PB4, 135 PB5, 136 PB6, 137 PB7, 139 PB8, 140 PB9
part C pins: 1 PE2, 2 PE3, 3 PE4, 4 PE5, 5 PE6, 10 PF0, 11 PF1, 12 PF2, 13 PF3, 14 PF4, 15 PF5, 18 PF6, 19 PF7, 20 PF8, 21 PF9, 22 PF10, 49 PF11, 50 PF12, 53 PF13, 54 PF14, 55 PF15, 56 PG0, 57 PG1, 58 PE7, 59 PE8, 60 PE9, 63 PE10, 64 PE11, 65 PE12, 66 PE13, 67 PE14, 68 PE15, 77 PD8, 78 PD9, 79 PD10, 80 PD11, 81 PD12, 82 PD13, 85 PD14, 86 PD15, 87 PG2, 88 PG3, 89 PG4, 90 PG5, 91 PG6, 92 PG7, 93 PG8, 114 PD0, 115 PD1, 116 PD2, 117 PD3, 118 PD4, 119 PD5, 122 PD6, 123 PD7, 124 PG9, 125 PG10, 126 PG11, 127 PG12, 128 PG13, 129 PG14, 132 PG15, 141 PE0, 142 PE1
part D pins: 16 VSS, 17 VDD, 31 VREF-, 32 VREF+, 38 VSS, 39 VDD, 51 VSS, 52 VDD, 61 VSS, 62 VDD, 70 VCAP, 71 VSS, 72 VDD, 83 VSS, 84 VDD, 94 VSS, 95 VDD, 107 VSS, 108 VDD, 120 VSS, 121 VDD, 130 VSS, 131 VDD, 143 VSS, 144 VDD

## IC_STM32C542RCT6
designator U?
part A pins: 2 PC13, 3 PC14 - OSC32_IN, 4 PC15 - OSC32_OUT, 5 PH0 - OSC_IN, 6 PH1 - OSC_OUT, 7 NRST, 8 PC0, 9 PC1, 10 PC2, 11 PC3, 14 PA0, 15 PA1, 16 PA2, 17 PA3, 20 PA4, 21 PA5, 22 PA6, 23 PA7, 24 PC4, 25 PC5, 26 PB0, 27 PB1, 28 PB2, 29 PB10, 33 PB12, 34 PB13, 35 PB14, 36 PB15, 37 PC6, 38 PC7, 39 PC8, 40 PC9, 41 PA8, 42 PA9, 43 PA10, 44 PA11, 45 PA12, 46 PA13 (JTMS/SWDIO), 49 PA14 (JTCK/SWCLK), 50 PA15 (JTDI), 51 PC10, 52 PC11, 53 PC12, 54 PD2, 55 (JTDO/TRACESWO) PB3 , 56 (NJTRST) PB4, 57 PB5, 58 PB6, 59 PB7, 60 PH2-BOOT0, 61 PB8
part B pins: 1 PE2, 12 VREF-, 13 VREF+, 18 VSS, 19 VDD, 30 VCAP, 31 VSS, 32 VDD, 47 VSS, 48 VDD, 62 PB9, 63 VSS, 64 VDD

## IC_STM32C562RET6
designator U?
part A pins: 2 PC13, 3 PC14 - OSC32_IN, 4 PC15 - OSC32_OUT, 5 PH0 - OSC_IN, 6 PH1 - OSC_OUT, 7 NRST, 8 PC0, 9 PC1, 10 PC2, 11 PC3, 14 PA0, 15 PA1, 16 PA2, 17 PA3, 20 PA4, 21 PA5, 22 PA6, 23 PA7, 24 PC4, 25 PC5, 26 PB0, 27 PB1, 28 PB2, 29 PB10, 33 PB12, 34 PB13, 35 PB14, 36 PB15, 37 PC6, 38 PC7, 39 PC8, 40 PC9, 41 PA8, 42 PA9, 43 PA10, 44 PA11, 45 PA12, 46 PA13 (JTMS/SWDIO), 49 PA14 (JTCK/SWCLK), 50 PA15 (JTDI), 51 PC10, 52 PC11, 53 PC12, 54 PD2, 55 (JTDO/TRACESWO) PB3 , 56 (NJTRST) PB4, 57 PB5, 58 PB6, 59 PB7, 60 PH2-BOOT0, 61 PB8
part B pins: 1 PE2, 12 VREF-, 13 VREF+, 18 VSS, 19 VDD, 30 VCAP, 31 VSS, 32 VDD, 47 VSS, 48 VDD, 62 PB9, 63 VSS, 64 VDD

## IC_STM32G564REZ3
designator U?
part A pins: 1 PC13, 2 NRST, 3 PC14 - OSC32_IN, 4 PC15 - OSC32_OUT, 7 PF10, 8 PH0 - OSC_IN, 9 PH1 - OSC_OUT, 10 PC0, 11 PC1, 12 PC2, 13 PC3, 14 PA0, 15 PA1, 16 PA2, 18 PA3, 19 PA4, 20 PA5, 21 PA6, 22 PA7, 23 PB0, 24 PB1, 25 PB2, 30 PB10, 31 PB11, 32 PB12, 33 PB13, 34 PB14, 35 PB15, 36 PD10, 39 PD11, 40 PD12, 41 PG2, 42 PG3, 43 PC11, 44 PC12, 45 PC6, 46 PC7, 47 PB5, 48 PB6, 49 PB7, 50 PA10, 51 PA11, 52 PA12, 53 PA8, 54 PA9, 55 PC8, 57 PB3, 58 PB4, 59 PA13, 60 PA14, 61 PA15, 62 BOOT0, 63 PB9, 64 PE2
part B pins: 5 VCAP, 6 VDD, 17 VDD, 26 VSSA, 27 VDDA, 28 VREF+, 29 VREF-, 37 VCAP, 38 VDD, 56 VDD, 65 EPAD - VSS

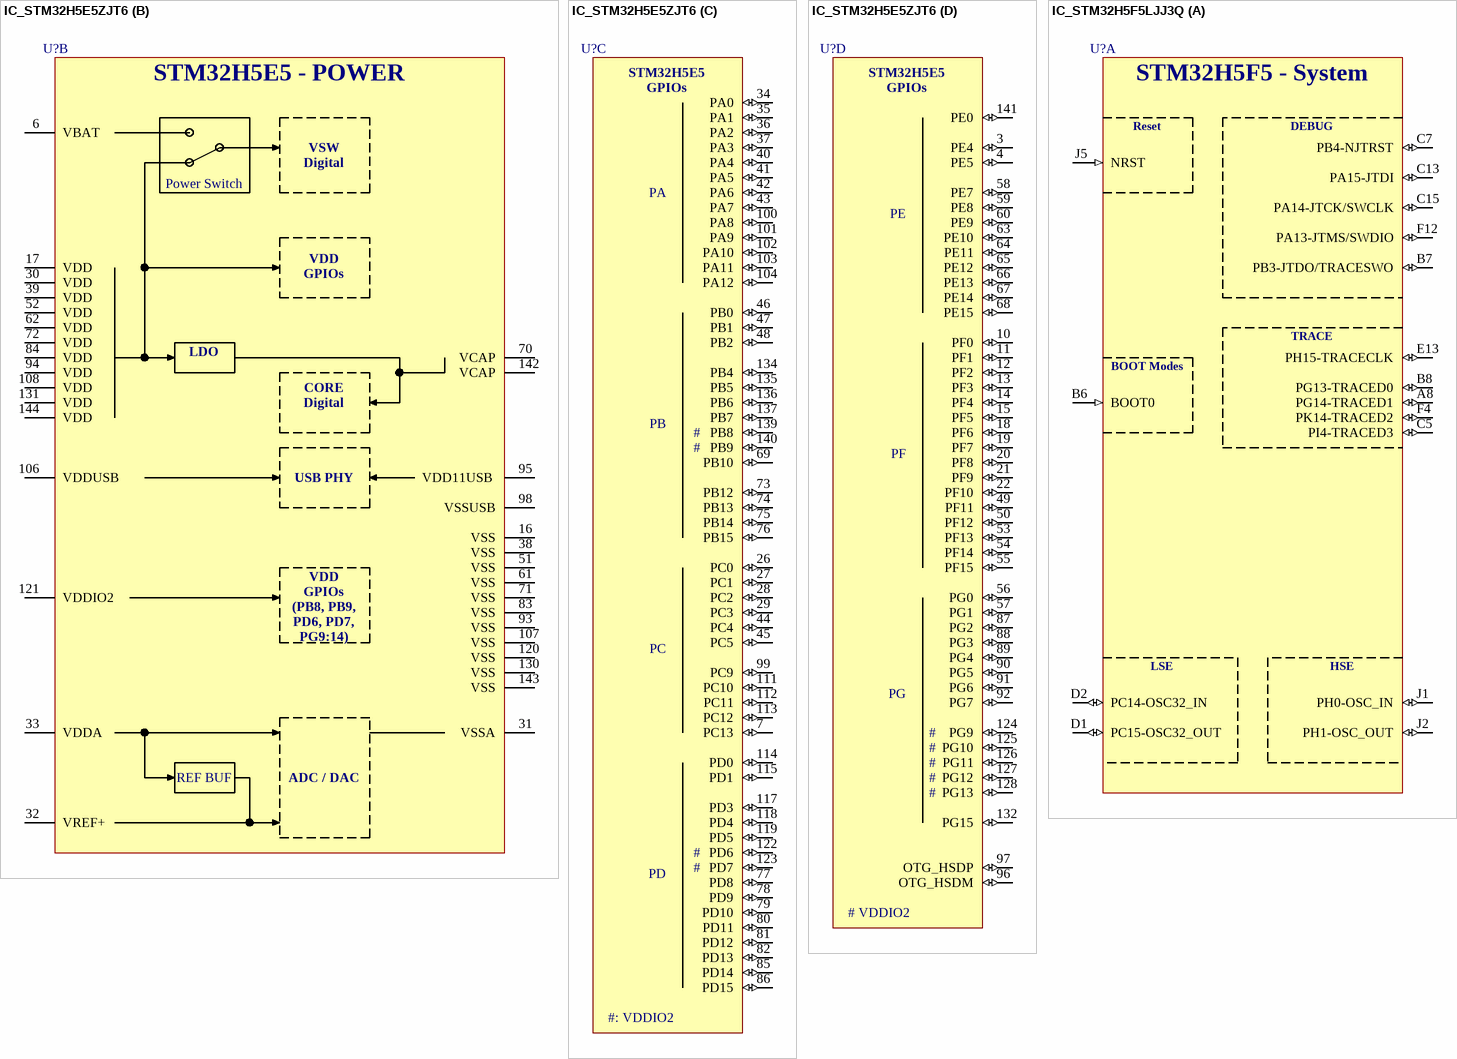
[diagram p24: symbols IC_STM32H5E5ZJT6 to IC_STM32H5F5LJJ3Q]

## IC_STM32H5E5ZJT6
designator U?
part A pins: 1 PE2-TRACECLK (io), 2 PE3-TRACED0 (io), 5 PE6-TRACED3 (io), 8 PC14-OSC32_IN (io), 9 PC15-OSC32_OUT (io), 23 PH0-OSC_IN (io), 24 PH1-OSC_OUT (io), 25 NRST (in), 105 PA13-JTMS/SWDIO (io), 109 PA14-JTCK/SWCLK (io), 110 PA15-JTDI (io), 116 PD2-TRACED2 (io), 129 PG14-TRACED1 (io), 133 PB3-JTDO/TRACESWO (io), 138 BOOT0 (in)
part B pins: 6 VBAT, 16 VSS, 17 VDD, 30 VDD, 31 VSSA, 32 VREF+, 33 VDDA, 38 VSS, 39 VDD, 51 VSS, 52 VDD, 61 VSS, 62 VDD, 70 VCAP, 71 VSS, 72 VDD, 83 VSS, 84 VDD, 93 VSS, 94 VDD, 95 VDD11USB , 98 VSSUSB, 106 VDDUSB, 107 VSS, 108 VDD, 120 VSS, 121 VDDIO2, 130 VSS, 131 VDD, 142 VCAP, 143 VSS, 144 VDD
part C pins: 7 PC13 (io), 26 PC0 (io), 27 PC1 (io), 28 PC2 (io), 29 PC3 (io), 34 PA0 (io), 35 PA1 (io), 36 PA2 (io), 37 PA3 (io), 40 PA4 (io), 41 PA5 (io), 42 PA6 (io), 43 PA7 (io), 44 PC4 (io), 45 PC5 (io), 46 PB0 (io), 47 PB1 (io), 48 PB2 (io), 69 PB10 (io), 73 PB12 (io), 74 PB13 (io), 75 PB14 (io), 76 PB15 (io), 77 PD8 (io), 78 PD9 (io), 79 PD10 (io), 80 PD11 (io), 81 PD12 (io), 82 PD13 (io), 85 PD14 (io), 86 PD15 (io), 99 PC9 (io), 100 PA8 (io), 101 PA9 (io), 102 PA10 (io), 103 PA11 (io), 104 PA12 (io), 111 PC10 (io), 112 PC11 (io), 113 PC12 (io), 114 PD0 (io), 115 PD1 (io), 117 PD3 (io), 118 PD4 (io), 119 PD5 (io), 122 PD6 (io), 123 PD7 (io), 134 PB4 (io), 135 PB5 (io), 136 PB6 (io), 137 PB7 (io), 139 PB8 (io), 140 PB9 (io)
part D pins: 3 PE4 (io), 4 PE5 (io), 10 PF0 (io), 11 PF1 (io), 12 PF2 (io), 13 PF3 (io), 14 PF4 (io), 15 PF5 (io), 18 PF6 (io), 19 PF7 (io), 20 PF8 (io), 21 PF9 (io), 22 PF10 (io), 49 PF11 (io), 50 PF12 (io), 53 PF13 (io), 54 PF14 (io), 55 PF15 (io), 56 PG0 (io), 57 PG1 (io), 58 PE7 (io), 59 PE8 (io), 60 PE9 (io), 63 PE10 (io), 64 PE11 (io), 65 PE12 (io), 66 PE13 (io), 67 PE14 (io), 68 PE15 (io), 87 PG2 (io), 88 PG3 (io), 89 PG4 (io), 90 PG5 (io), 91 PG6 (io), 92 PG7 (io), 96 OTG_HSDM (io), 97 OTG_HSDP (io), 124 PG9 (io), 125 PG10 (io), 126 PG11 (io), 127 PG12 (io), 128 PG13 (io), 132 PG15 (io), 141 PE0 (io)

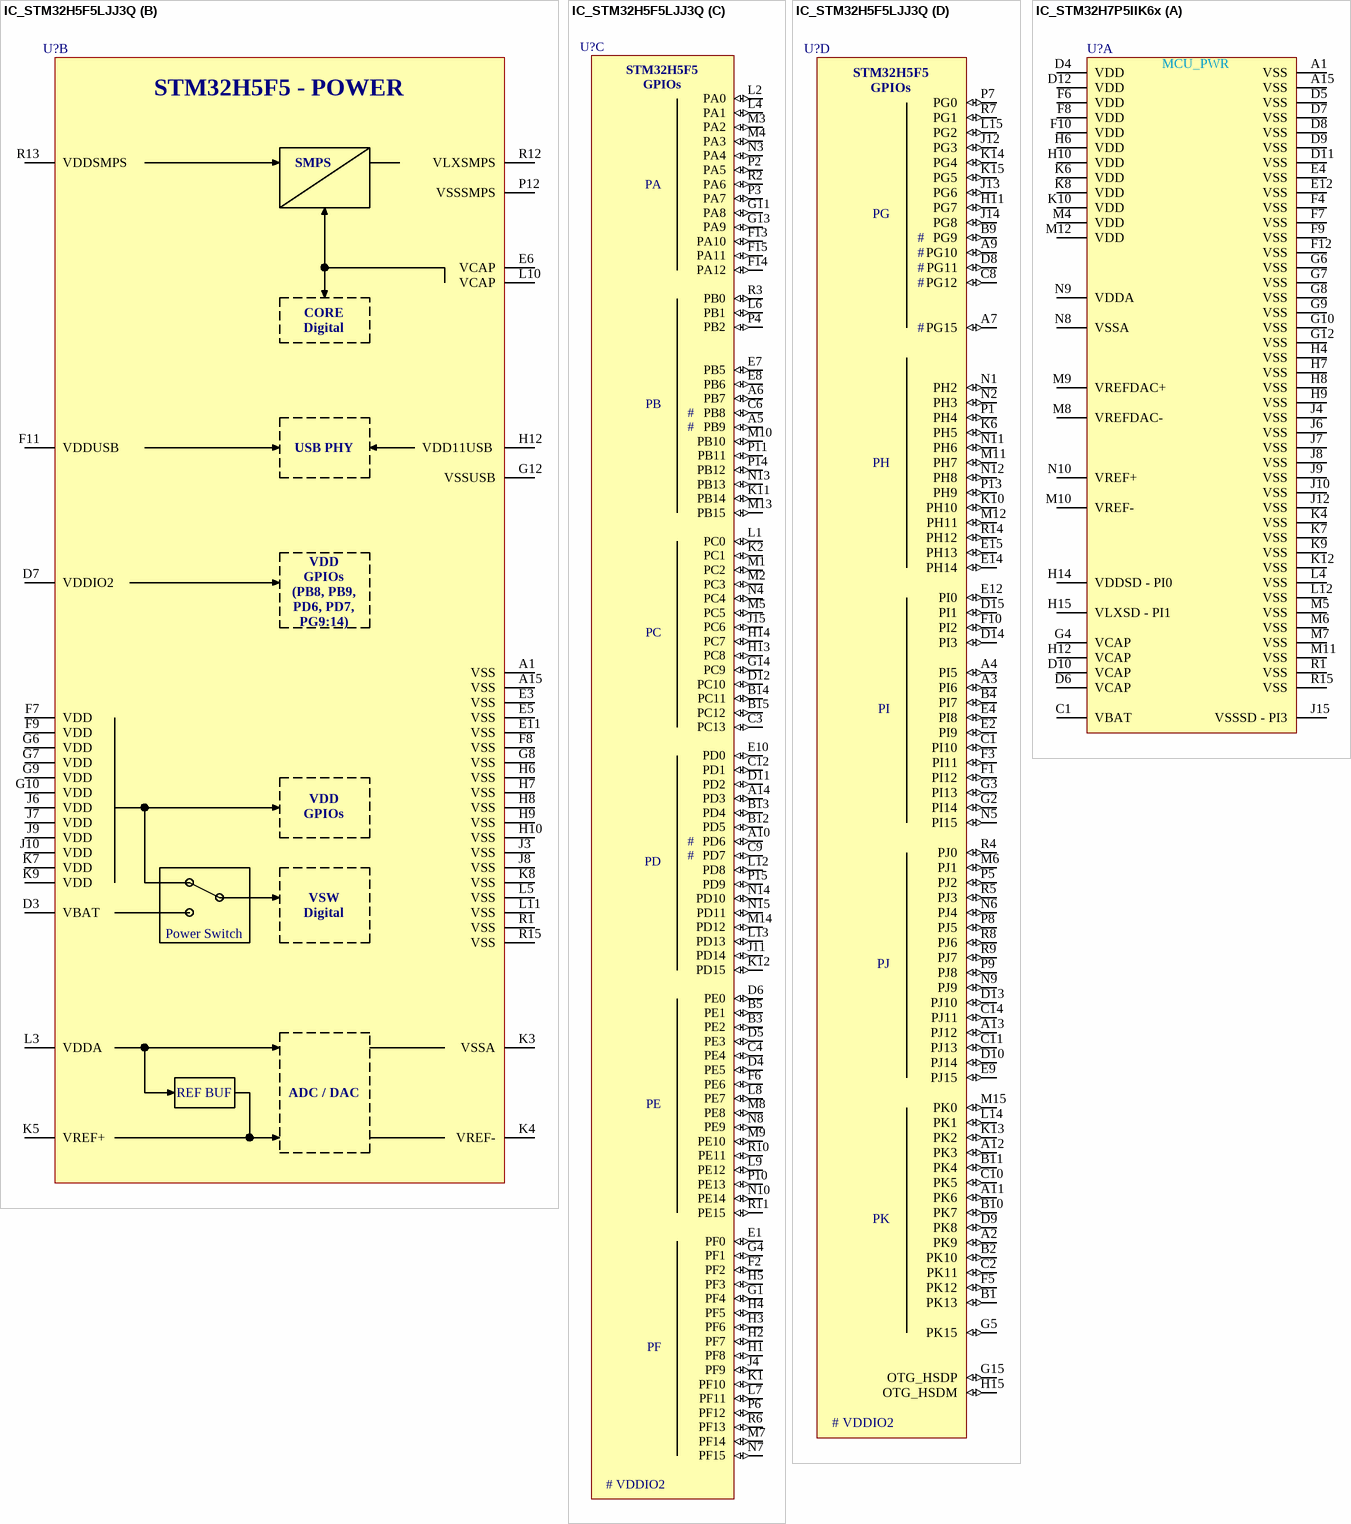
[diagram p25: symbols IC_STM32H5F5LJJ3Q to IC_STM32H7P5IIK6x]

## IC_STM32H5F5LJJ3Q
designator U?
part A pins: A8 PG14-TRACED1 (io), B6 BOOT0 (in), B7 PB3-JTDO/TRACESWO (io), B8 PG13-TRACED0 (io), C5 PI4-TRACED3 (io), C7 PB4-NJTRST (io), C13 PA15-JTDI (io), C15 PA14-JTCK/SWCLK (io), D1 PC15-OSC32_OUT (io), D2 PC14-OSC32_IN (io), E13 PH15-TRACECLK (io), F4 PK14-TRACED2 (io), F12 PA13-JTMS/SWDIO (io), J1 PH0-OSC_IN (io), J2 PH1-OSC_OUT (io), J5 NRST (in)
part B pins: A1 VSS, A15 VSS, D3 VBAT, D7 VDDIO2, E3 VSS, E5 VSS, E6 VCAP, E11 VSS, F7 VDD, F8 VSS, F9 VDD, F11 VDDUSB, G6 VDD, G7 VDD, G8 VSS, G9 VDD, G10 VDD, G12 VSSUSB, H6 VSS, H7 VSS, H8 VSS, H9 VSS, H10 VSS, H12 VDD11USB , J3 VSS, J6 VDD, J7 VDD, J8 VSS, J9 VDD, J10 VDD, K3 VSSA, K4 VREF-, K5 VREF+, K7 VDD, K8 VSS, K9 VDD, L3 VDDA, L5 VSS, L10 VCAP, L11 VSS, P12 VSSSMPS, R1 VSS, R12 VLXSMPS, R13 VDDSMPS, R15 VSS
part C pins: A5 PB9 (io), A6 PB7 (io), A10 PD6 (io), A14 PD3 (io), B3 PE2 (io), B5 PE1 (io), B12 PD5 (io), B13 PD4 (io), B14 PC11 (io), B15 PC12 (io), C3 PC13 (io), C4 PE4 (io), C6 PB8 (io), C9 PD7 (io), C12 PD1 (io), D4 PE5 (io), D5 PE3 (io), D6 PE0 (io), D11 PD2 (io), D12 PC10 (io), E1 PF0 (io), E7 PB5 (io), E8 PB6 (io), E10 PD0 (io), F2 PF2 (io), F6 PE6 (io), F13 PA10 (io), F14 PA12 (io), F15 PA11 (io), G1 PF4 (io), G4 PF1 (io), G11 PA8 (io), G13 PA9 (io), G14 PC9 (io), H1 PF8 (io), H2 PF7 (io), H3 PF6 (io), H4 PF5 (io), H5 PF3 (io), H13 PC8 (io), H14 PC7 (io), J4 PF9 (io), J11 PD14 (io), J15 PC6 (io), K1 PF10 (io), K2 PC1 (io), K11 PB14 (io), K12 PD15 (io), L1 PC0 (io), L2 PA0 (io), L4 PA1 (io), L6 PB1 (io), L7 PF11 (io), L8 PE7 (io), L9 PE12 (io), L12 PD8 (io), L13 PD13 (io), M1 PC2 (io), M2 PC3 (io), M3 PA2 (io), M4 PA3 (io), M5 PC5 (io), M7 PF14 (io), M8 PE8 (io), M9 PE10 (io), M10 PB10 (io), M13 PB15 (io), M14 PD12 (io), N3 PA4 (io), N4 PC4 (io), N7 PF15 (io), N8 PE9 (io), N10 PE14 (io), N13 PB13 (io), N14 PD10 (io), N15 PD11 (io), P2 PA5 (io), P3 PA7 (io), P4 PB2 (io), P6 PF12 (io), P10 PE13 (io), P11 PB11 (io), P14 PB12 (io), P15 PD9 (io), R2 PA6 (io), R3 PB0 (io), R6 PF13 (io), R10 PE11 (io), R11 PE15 (io)
part D pins: A2 PK9 (io), A3 PI6 (io), A4 PI5 (io), A7 PG15 (io), A9 PG10 (io), A11 PK6 (io), A12 PK3 (io), A13 PJ12 (io), B1 PK13 (io), B2 PK10 (io), B4 PI7 (io), B9 PG9 (io), B10 PK7 (io), B11 PK4 (io), C1 PI10 (io), C2 PK11 (io), C8 PG12 (io), C10 PK5 (io), C11 PJ13 (io), C14 PJ11 (io), D8 PG11 (io), D9 PK8 (io), D10 PJ14 (io), D13 PJ10 (io), D14 PI3 (io), D15 PI1 (io), E2 PI9 (io), E4 PI8 (io), E9 PJ15 (io), E12 PI0 (io), E14 PH14 (io), E15 PH13 (io), F1 PI12 (io), F3 PI11 (io), F5 PK12 (io), F10 PI2 (io), G2 PI14 (io), G3 PI13 (io), G5 PK15 (io), G15 OTG_HSDP (io), H11 PG7 (io), H15 OTG_HSDM (io), J12 PG3 (io), J13 PG6 (io), J14 PG8 (io), K6 PH5 (io), K10 PH10 (io), K13 PK2 (io), K14 PG4 (io), K15 PG5 (io), L14 PK1 (io), L15 PG2 (io), M6 PJ1 (io), M11 PH7 (io), M12 PH11 (io), M15 PK0 (io), N1 PH2 (io), N2 PH3 (io), N5 PI15 (io), N6 PJ4 (io), N9 PJ9 (io), N11 PH6 (io), N12 PH8 (io), P1 PH4 (io), P5 PJ2 (io), P7 PG0 (io), P8 PJ5 (io), P9 PJ8 (io), P13 PH9 (io), R4 PJ0 (io), R5 PJ3 (io), R7 PG1 (io), R8 PJ6 (io), R9 PJ7 (io), R14 PH12 (io)

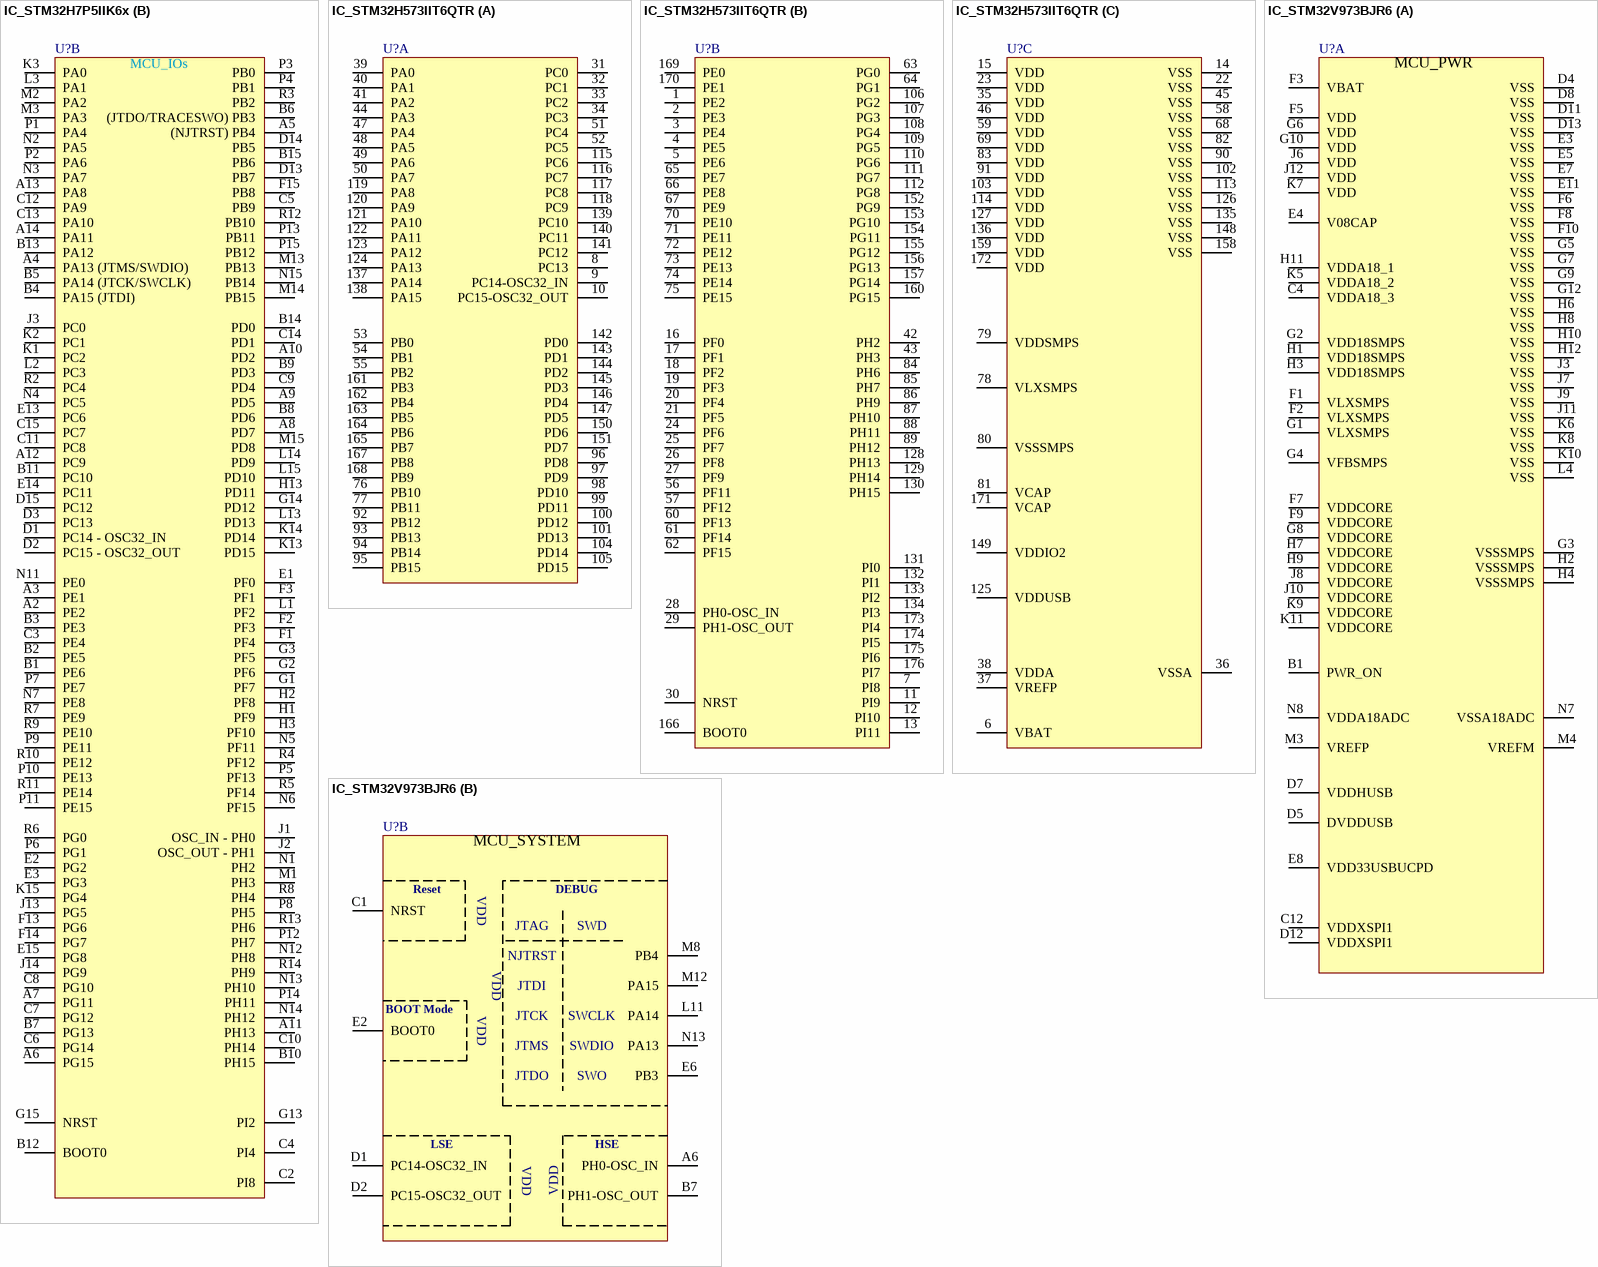
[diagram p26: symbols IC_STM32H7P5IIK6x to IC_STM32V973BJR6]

## IC_STM32H7P5IIK6x
designator U?
part A pins: A1 VSS, A15 VSS, C1 VBAT, D4 VDD, D5 VSS, D6 VCAP, D7 VSS, D8 VSS, D9 VSS, D10 VCAP, D11 VSS, D12 VDD, E4 VSS, E12 VSS, F4 VSS, F6 VDD, F7 VSS, F8 VDD, F9 VSS, F10 VDD, F12 VSS, G4 VCAP, G6 VSS, G7 VSS, G8 VSS, G9 VSS, G10 VSS, G12 VSS, H4 VSS, H6 VDD, H7 VSS, H8 VSS, H9 VSS, H10 VDD, H12 VCAP, H14 VDDSD - PI0, H15 VLXSD - PI1, J4 VSS, J6 VSS, J7 VSS, J8 VSS, J9 VSS, J10 VSS, J12 VSS, J15 VSSSD - PI3, K4 VSS, K6 VDD, K7 VSS, K8 VDD, K9 VSS, K10 VDD, K12 VSS, L4 VSS, L12 VSS, M4 VDD, M5 VSS, M6 VSS, M7 VSS, M8 VREFDAC-, M9 VREFDAC+, M10 VREF-, M11 VSS, M12 VDD, N8 VSSA, N9 VDDA, N10 VREF+, R1 VSS, R15 VSS
part B pins: A2 PE2, A3 PE1, A4 PA13 (JTMS/SWDIO), A5 (NJTRST) PB4, A6 PG15, A7 PG11, A8 PD7, A9 PD5, A10 PD2, A11 PH13, A12 PC9, A13 PA8, A14 PA11, B1 PE6, B2 PE5, B3 PE3, B4 PA15 (JTDI), B5 PA14 (JTCK/SWCLK), B6 (JTDO/TRACESWO) PB3, B7 PG13, B8 PD6, B9 PD3, B10 PH15, B11 PC10, B12 BOOT0, B13 PA12, B14 PD0, B15 PB6, C2 PI8, C3 PE4, C4 PI4, C5 PB9, C6 PG14, C7 PG12, C8 PG10, C9 PD4, C10 PH14, C11 PC8, C12 PA9, C13 PA10, C14 PD1, C15 PC7, D1 PC14 - OSC32_IN, D2 PC15 - OSC32_OUT, D3 PC13, D13 PB7, D14 PB5, D15 PC12, E1 PF0, E2 PG2, E3 PG3, E13 PC6, E14 PC11, E15 PG8, F1 PF4, F2 PF3, F3 PF1, F13 PG6, F14 PG7, F15 PB8, G1 PF7, G2 PF6, G3 PF5, G13 PI2, G14 PD12, G15 NRST, H1 PF9, H2 PF8, H3 PF10, H13 PD11, J1 OSC_IN - PH0, J2 OSC_OUT - PH1, J3 PC0, J13 PG5, J14 PG9, K1 PC2, K2 PC1, K3 PA0, K13 PD15, K14 PD14, K15 PG4, L1 PF2, L2 PC3, L3 PA1, L13 PD13, L14 PD9, L15 PD10, M1 PH3, M2 PA2, M3 PA3, M13 PB13, M14 PB15, M15 PD8, N1 PH2, N2 PA5, N3 PA7, N4 PC5, N5 PF11, N6 PF15, N7 PE8, N11 PE0, N12 PH8, N13 PH10, N14 PH12, N15 PB14, P1 PA4, P2 PA6, P3 PB0, P4 PB1, P5 PF13, P6 PG1, P7 PE7, P8 PH5, P9 PE11, P10 PE13, P11 PE15, P12 PH7, P13 PB11, P14 PH11, P15 PB12, R2 PC4, R3 PB2, R4 PF12, R5 PF14, R6 PG0, R7 PE9, R8 PH4, R9 PE10, R10 PE12, R11 PE14, R12 PB10, R13 PH6, R14 PH9
1 alternate drawing of the same symbol

## IC_STM32H573IIT6QTR
designator U?
part A pins: 8 PC13, 9 PC14-OSC32_IN, 10 PC15-OSC32_OUT, 31 PC0, 32 PC1, 33 PC2, 34 PC3, 39 PA0, 40 PA1, 41 PA2, 44 PA3, 47 PA4, 48 PA5, 49 PA6, 50 PA7, 51 PC4, 52 PC5, 53 PB0, 54 PB1, 55 PB2, 76 PB10, 77 PB11, 92 PB12, 93 PB13, 94 PB14, 95 PB15, 96 PD8, 97 PD9, 98 PD10, 99 PD11, 100 PD12, 101 PD13, 104 PD14, 105 PD15, 115 PC6, 116 PC7, 117 PC8, 118 PC9, 119 PA8, 120 PA9, 121 PA10, 122 PA11, 123 PA12, 124 PA13, 137 PA14, 138 PA15, 139 PC10, 140 PC11, 141 PC12, 142 PD0, 143 PD1, 144 PD2, 145 PD3, 146 PD4, 147 PD5, 150 PD6, 151 PD7, 161 PB3, 162 PB4, 163 PB5, 164 PB6, 165 PB7, 167 PB8, 168 PB9
part B pins: 1 PE2, 2 PE3, 3 PE4, 4 PE5, 5 PE6, 7 PI8, 11 PI9, 12 PI10, 13 PI11, 16 PF0, 17 PF1, 18 PF2, 19 PF3, 20 PF4, 21 PF5, 24 PF6, 25 PF7, 26 PF8, 27 PF9, 28 PH0-OSC_IN, 29 PH1-OSC_OUT, 30 NRST, 42 PH2, 43 PH3, 56 PF11, 57 PF12, 60 PF13, 61 PF14, 62 PF15, 63 PG0, 64 PG1, 65 PE7, 66 PE8, 67 PE9, 70 PE10, 71 PE11, 72 PE12, 73 PE13, 74 PE14, 75 PE15, 84 PH6, 85 PH7, 86 PH9, 87 PH10, 88 PH11, 89 PH12, 106 PG2, 107 PG3, 108 PG4, 109 PG5, 110 PG6, 111 PG7, 112 PG8, 128 PH13, 129 PH14, 130 PH15, 131 PI0, 132 PI1, 133 PI2, 134 PI3, 152 PG9, 153 PG10, 154 PG11, 155 PG12, 156 PG13, 157 PG14, 160 PG15, 166 BOOT0, 169 PE0, 170 PE1, 173 PI4, 174 PI5, 175 PI6, 176 PI7
part C pins: 6 VBAT, 14 VSS, 15 VDD, 22 VSS, 23 VDD, 35 VDD, 36 VSSA, 37 VREFP, 38 VDDA, 45 VSS, 46 VDD, 58 VSS, 59 VDD, 68 VSS, 69 VDD, 78 VLXSMPS, 79 VDDSMPS, 80 VSSSMPS, 81 VCAP, 82 VSS, 83 VDD, 90 VSS, 91 VDD, 102 VSS, 103 VDD, 113 VSS, 114 VDD, 125 VDDUSB, 126 VSS, 127 VDD, 135 VSS, 136 VDD, 148 VSS, 149 VDDIO2, 158 VSS, 159 VDD, 171 VCAP, 172 VDD

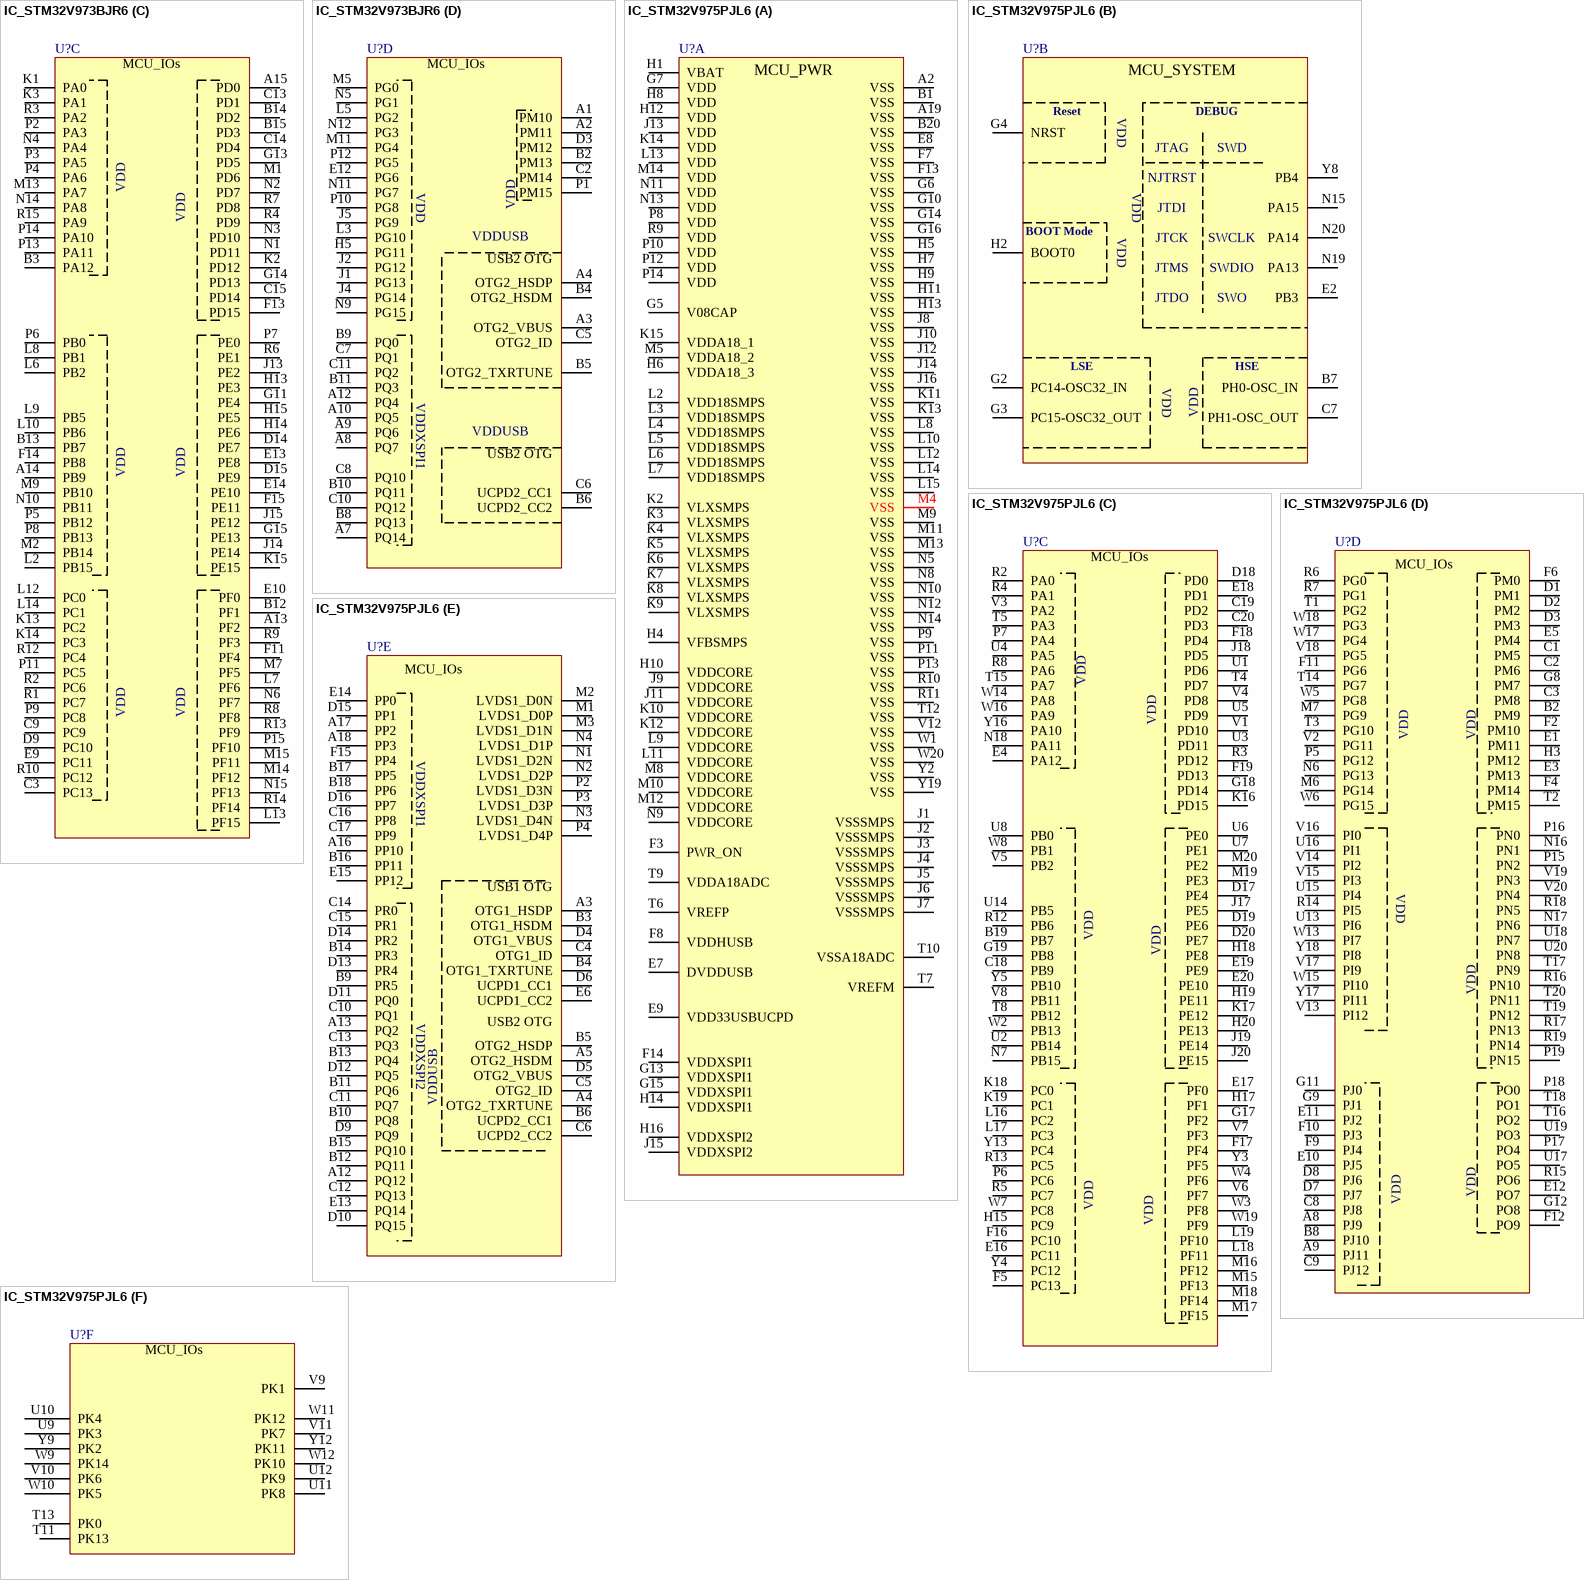
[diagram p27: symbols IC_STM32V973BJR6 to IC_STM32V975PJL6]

## IC_STM32V973BJR6
designator U?
part A pins: B1 PWR_ON, C4 VDDA18_3, C12 VDDXSPI1, D4 VSS, D5 DVDDUSB, D7 VDDHUSB, D8 VSS, D11 VSS, D12 VDDXSPI1, D13 VSS, E3 VSS, E4 V08CAP, E5 VSS, E7 VSS, E8 VDD33USBUCPD, E11 VSS, F1 VLXSMPS, F2 VLXSMPS, F3 VBAT, F5 VDD, F6 VSS, F7 VDDCORE, F8 VSS, F9 VDDCORE, F10 VSS, G1 VLXSMPS, G2 VDD18SMPS, G3 VSSSMPS, G4 VFBSMPS, G5 VSS, G6 VDD, G7 VSS, G8 VDDCORE, G9 VSS, G10 VDD, G12 VSS, H1 VDD18SMPS, H2 VSSSMPS, H3 VDD18SMPS, H4 VSSSMPS, H6 VSS, H7 VDDCORE, H8 VSS, H9 VDDCORE, H10 VSS, H11 VDDA18_1, H12 VSS, J3 VSS, J6 VDD, J7 VSS, J8 VDDCORE, J9 VSS, J10 VDDCORE, J11 VSS, J12 VDD, K5 VDDA18_2, K6 VSS, K7 VDD, K8 VSS, K9 VDDCORE, K10 VSS, K11 VDDCORE, L4 VSS, M3 VREFP, M4 VREFM, N7 VSSA18ADC, N8 VDDA18ADC
part B pins: A6 PH0-OSC_IN, B7 PH1-OSC_OUT, C1 NRST, D1 PC14-OSC32_IN, D2 PC15-OSC32_OUT, E2 BOOT0, E6 PB3, L11 PA14, M8 PB4, M12 PA15, N13 PA13
part C pins: A13 PF2, A14 PB9, A15 PD0, B3 PA12, B12 PF1, B13 PB7, B14 PD2, B15 PD3, C3 PC13, C9 PC9, C13 PD1, C14 PD4, C15 PD14, D9 PC10, D14 PE7, D15 PE9, E9 PC11, E10 PF0, E13 PE8, E14 PE10, F11 PF4, F13 PD15, F14 PB8, F15 PE11, G11 PE4, G13 PD5, G14 PD13, G15 PE13, H13 PE3, H14 PE6, H15 PE5, J13 PE2, J14 PE14, J15 PE12, K1 PA0, K2 PD12, K3 PA1, K13 PC2, K14 PC3, K15 PE15, L2 PB15, L6 PB2, L7 PF6, L8 PB1, L9 PB5, L10 PB6, L12 PC0, L13 PF15, L14 PC1, M1 PD6, M2 PB14, M7 PF5, M9 PB10, M13 PA7, M14 PF12, M15 PF11, N1 PD11, N2 PD7, N3 PD10, N4 PA4, N6 PF7, N10 PB11, N14 PA8, N15 PF13, P2 PA3, P3 PA5, P4 PA6, P5 PB12, P6 PB0, P7 PE0, P8 PB13, P9 PC8, P11 PC5, P13 PA11, P14 PA10, P15 PF10, R1 PC7, R2 PC6, R3 PA2, R4 PD9, R6 PE1, R7 PD8, R8 PF8, R9 PF3, R10 PC12, R12 PC4, R13 PF9, R14 PF14, R15 PA9
part D pins: A1 PM10, A2 PM11, A3 OTG2_VBUS, A4 OTG2_HSDP, A7 PQ14, A8 PQ7, A9 PQ6, A10 PQ5, A12 PQ4, B2 PM13, B4 OTG2_HSDM, B5 OTG2_TXRTUNE, B6 UCPD2_CC2, B8 PQ13, B9 PQ0, B10 PQ11, B11 PQ3, C2 PM14, C5 OTG2_ID, C6 UCPD2_CC1, C7 PQ1, C8 PQ10, C10 PQ12, C11 PQ2, D3 PM12, E12 PG6, H5 PG11, J1 PG13, J2 PG12, J4 PG14, J5 PG9, L3 PG10, L5 PG2, M5 PG0, M11 PG4, N5 PG1, N9 PG15, N11 PG7, N12 PG3, P1 PM15, P10 PG8, P12 PG5
1 alternate drawing of the same symbol

## IC_STM32V975PJL6
designator U?
part A pins: A2 VSS, A19 VSS, B1 VSS, B20 VSS, E7 DVDDUSB, E8 VSS, E9 VDD33USBUCPD, F3 PWR_ON, F7 VSS, F8 VDDHUSB, F13 VSS, F14 VDDXSPI1, G5 V08CAP, G6 VSS, G7 VDD, G10 VSS, G13 VDDXSPI1, G14 VSS, G15 VDDXSPI1, G16 VSS, H1 VBAT, H4 VFBSMPS, H5 VSS, H6 VDDA18_3, H7 VSS, H8 VDD, H9 VSS, H10 VDDCORE, H11 VSS, H12 VDD, H13 VSS, H14 VDDXSPI1, H16 VDDXSPI2, J1 VSSSMPS, J2 VSSSMPS, J3 VSSSMPS, J4 VSSSMPS, J5 VSSSMPS, J6 VSSSMPS, J7 VSSSMPS, J8 VSS, J9 VDDCORE, J10 VSS, J11 VDDCORE, J12 VSS, J13 VDD, J14 VSS, J15 VDDXSPI2, J16 VSS, K2 VLXSMPS, K3 VLXSMPS, K4 VLXSMPS, K5 VLXSMPS, K6 VLXSMPS, K7 VLXSMPS, K8 VLXSMPS, K9 VLXSMPS, K10 VDDCORE, K11 VSS, K12 VDDCORE, K13 VSS, K14 VDD, K15 VDDA18_1, L2 VDD18SMPS, L3 VDD18SMPS, L4 VDD18SMPS, L5 VDD18SMPS, L6 VDD18SMPS, L7 VDD18SMPS, L8 VSS, L9 VDDCORE, L10 VSS, L11 VDDCORE, L12 VSS, L13 VDD, L14 VSS, L15 VSS, M4 VSS, M5 VDDA18_2, M8 VDDCORE, M9 VSS, M10 VDDCORE, M11 VSS, M12 VDDCORE, M13 VSS, M14 VDD, N5 VSS, N8 VSS, N9 VDDCORE, N10 VSS, N11 VDD, N12 VSS, N13 VDD, N14 VSS, P8 VDD, P9 VSS, P10 VDD, P11 VSS, P12 VDD, P13 VSS, P14 VDD, R9 VDD, R10 VSS, R11 VSS, T6 VREFP, T7 VREFM, T9 VDDA18ADC, T10 VSSA18ADC, T12 VSS, V12 VSS, W1 VSS, W20 VSS, Y2 VSS, Y19 VSS
part B pins: B7 PH0-OSC_IN, C7 PH1-OSC_OUT, E2 PB3, G2 PC14-OSC32_IN, G3 PC15-OSC32_OUT, G4 NRST, H2 BOOT0, N15 PA15, N19 PA13, N20 PA14, Y8 PB4
part C pins: B19 PB7, C18 PB9, C19 PD2, C20 PD3, D17 PE4, D18 PD0, D19 PE6, D20 PE7, E4 PA12, E16 PC11, E17 PF0, E18 PD1, E19 PE9, E20 PE10, F5 PC13, F16 PC10, F17 PF4, F18 PD4, F19 PD13, G17 PF2, G18 PD14, G19 PB8, H15 PC9, H17 PF1, H18 PE8, H19 PE11, H20 PE13, J17 PE5, J18 PD5, J19 PE14, J20 PE15, K16 PD15, K17 PE12, K18 PC0, K19 PC1, L16 PC2, L17 PC3, L18 PF11, L19 PF10, M15 PF13, M16 PF12, M17 PF15, M18 PF14, M19 PE3, M20 PE2, N7 PB15, N18 PA11, P6 PC6, P7 PA4, R2 PA0, R3 PD12, R4 PA1, R5 PC7, R8 PA6, R12 PB6, R13 PC5, T4 PD7, T5 PA3, T8 PB12, T15 PA7, U1 PD6, U2 PB14, U3 PD11, U4 PA5, U5 PD9, U6 PE0, U7 PE1, U8 PB0, U14 PB5, V1 PD10, V3 PA2, V4 PD8, V5 PB2, V6 PF7, V7 PF3, V8 PB11, W2 PB13, W3 PF8, W4 PF6, W7 PC8, W8 PB1, W14 PA8, W16 PA9, W19 PF9, Y3 PF5, Y4 PC12, Y5 PB10, Y13 PC4, Y16 PA10
part D pins: A8 PJ9, A9 PJ11, B2 PM9, B8 PJ10, C1 PM5, C2 PM6, C3 PM8, C8 PJ8, C9 PJ12, D1 PM1, D2 PM2, D3 PM3, D7 PJ7, D8 PJ6, E1 PM11, E3 PM13, E5 PM4, E10 PJ5, E11 PJ2, E12 PO7, F2 PM10, F4 PM14, F6 PM0, F9 PJ4, F10 PJ3, F11 PG6, F12 PO9, G8 PM7, G9 PJ1, G11 PJ0, G12 PO8, H3 PM12, M6 PG14, M7 PG9, N6 PG13, N16 PN1, N17 PN6, P5 PG12, P15 PN2, P16 PN0, P17 PO4, P18 PO0, P19 PN15, R6 PG0, R7 PG1, R14 PI5, R15 PO6, R16 PN10, R17 PN13, R18 PN5, R19 PN14, T1 PG2, T2 PM15, T3 PG10, T14 PG7, T16 PO2, T17 PN9, T18 PO1, T19 PN12, T20 PN11, U13 PI6, U15 PI4, U16 PI1, U17 PO5, U18 PN7, U19 PO3, U20 PN8, V2 PG11, V13 PI12, V14 PI2, V15 PI3, V16 PI0, V17 PI9, V18 PG5, V19 PN3, V20 PN4, W5 PG8, W6 PG15, W13 PI7, W15 PI10, W17 PG4, W18 PG3, Y17 PI11, Y18 PI8
part E pins: A3 OTG1_HSDP, A4 OTG2_TXRTUNE, A5 OTG2_HSDM, A12 PQ12, A13 PQ2, A16 PP10, A17 PP2, A18 PP3, B3 OTG1_HSDM, B4 OTG1_TXRTUNE, B5 OTG2_HSDP, B6 UCPD2_CC1, B9 PR5, B10 PQ8, B11 PQ6, B12 PQ11, B13 PQ4, B14 PR3, B15 PQ10, B16 PP11, B17 PP5, B18 PP6, C4 OTG1_ID, C5 OTG2_ID, C6 UCPD2_CC2, C10 PQ1, C11 PQ7, C12 PQ13, C13 PQ3, C14 PR0, C15 PR1, C16 PP8, C17 PP9, D4 OTG1_VBUS, D5 OTG2_VBUS, D6 UCPD1_CC1, D9 PQ9, D10 PQ15, D11 PQ0, D12 PQ5, D13 PR4, D14 PR2, D15 PP1, D16 PP7, E6 UCPD1_CC2, E13 PQ14, E14 PP0, E15 PP12, F15 PP4, M1 LVDS1_D0P, M2 LVDS1_D0N, M3 LVDS1_D1N, N1 LVDS1_D2N, N2 LVDS1_D2P, N3 LVDS1_D4N, N4 LVDS1_D1P, P2 LVDS1_D3N, P3 LVDS1_D3P, P4 LVDS1_D4P
part F pins: T11 PK13, T13 PK0, U9 PK3, U10 PK4, U11 PK8, U12 PK9, V9 PK1, V10 PK6, V11 PK7, W9 PK14, W10 PK5, W11 PK12, W12 PK10, Y9 PK2, Y12 PK11
1 alternate drawing of the same symbol

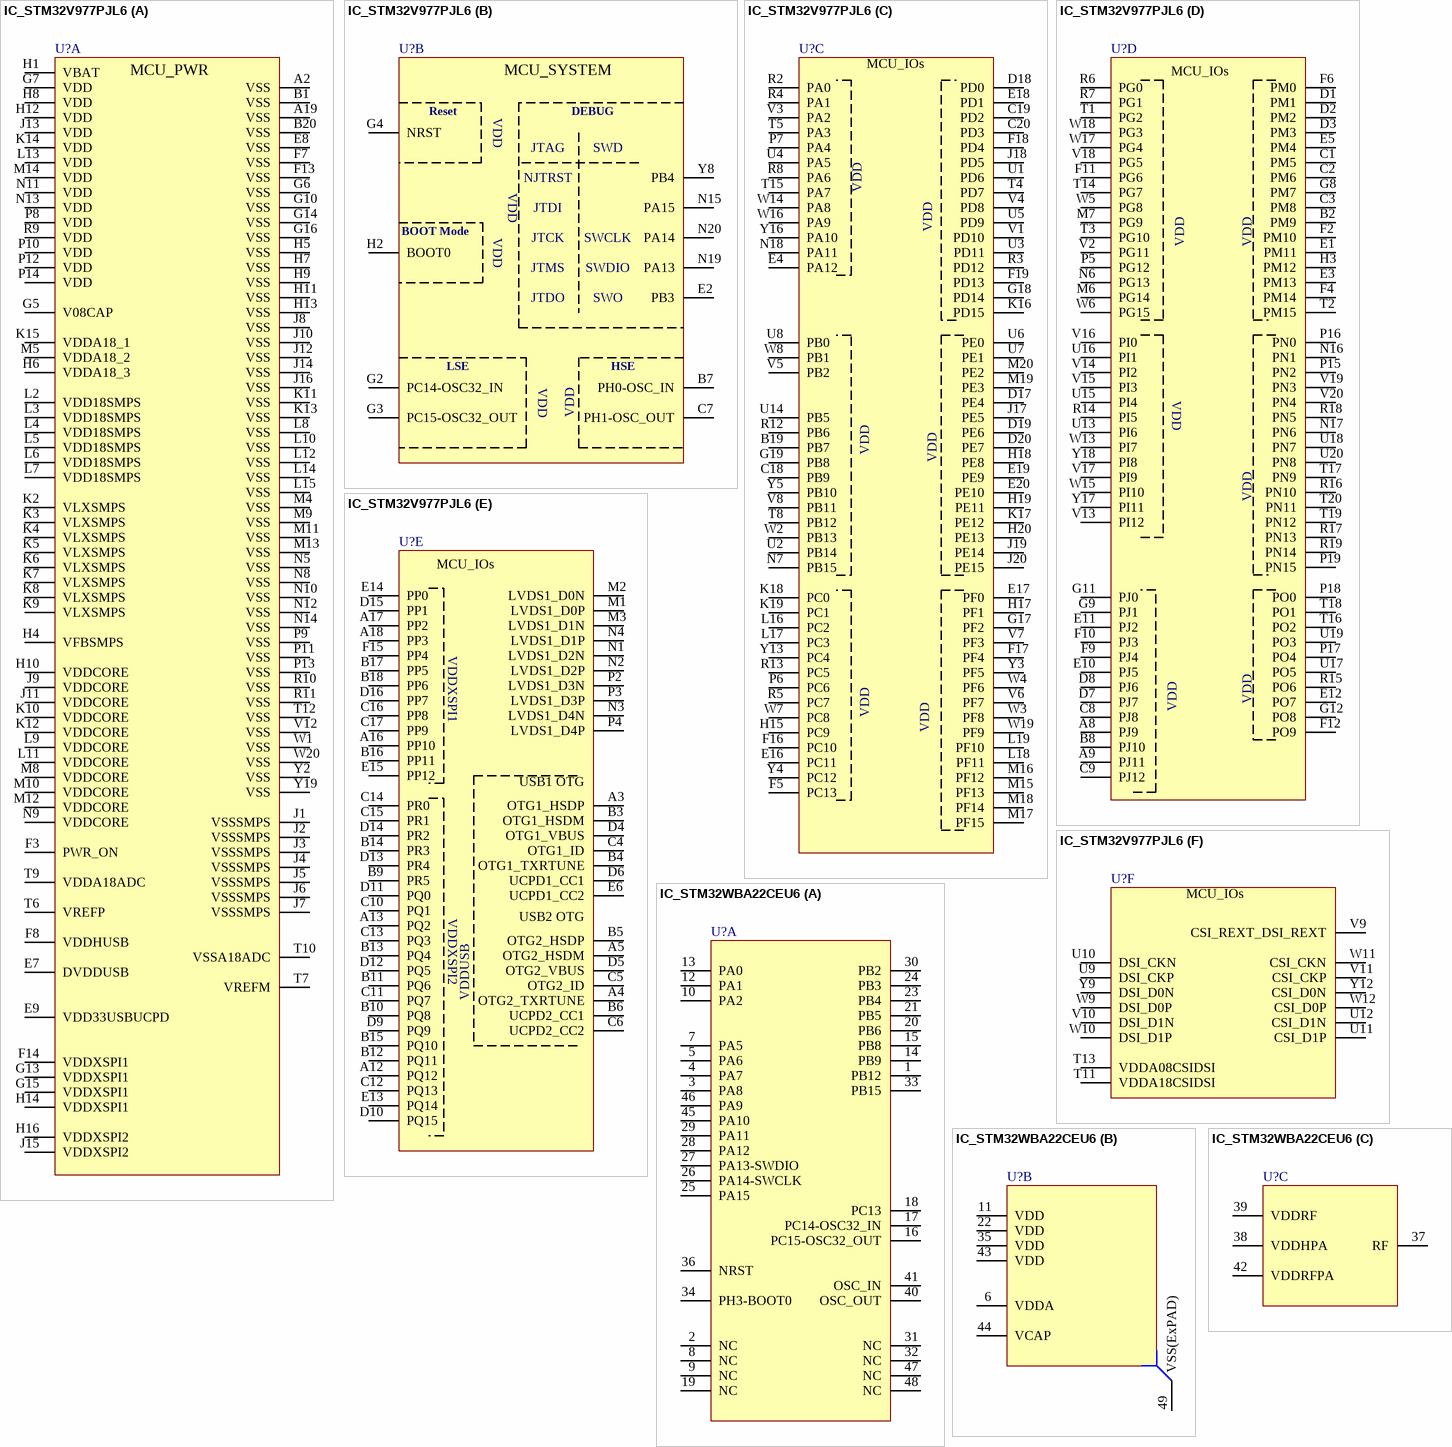
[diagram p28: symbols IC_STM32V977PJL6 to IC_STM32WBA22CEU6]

## IC_STM32V977PJL6
designator U?
part A pins: A2 VSS, A19 VSS, B1 VSS, B20 VSS, E7 DVDDUSB, E8 VSS, E9 VDD33USBUCPD, F3 PWR_ON, F7 VSS, F8 VDDHUSB, F13 VSS, F14 VDDXSPI1, G5 V08CAP, G6 VSS, G7 VDD, G10 VSS, G13 VDDXSPI1, G14 VSS, G15 VDDXSPI1, G16 VSS, H1 VBAT, H4 VFBSMPS, H5 VSS, H6 VDDA18_3, H7 VSS, H8 VDD, H9 VSS, H10 VDDCORE, H11 VSS, H12 VDD, H13 VSS, H14 VDDXSPI1, H16 VDDXSPI2, J1 VSSSMPS, J2 VSSSMPS, J3 VSSSMPS, J4 VSSSMPS, J5 VSSSMPS, J6 VSSSMPS, J7 VSSSMPS, J8 VSS, J9 VDDCORE, J10 VSS, J11 VDDCORE, J12 VSS, J13 VDD, J14 VSS, J15 VDDXSPI2, J16 VSS, K2 VLXSMPS, K3 VLXSMPS, K4 VLXSMPS, K5 VLXSMPS, K6 VLXSMPS, K7 VLXSMPS, K8 VLXSMPS, K9 VLXSMPS, K10 VDDCORE, K11 VSS, K12 VDDCORE, K13 VSS, K14 VDD, K15 VDDA18_1, L2 VDD18SMPS, L3 VDD18SMPS, L4 VDD18SMPS, L5 VDD18SMPS, L6 VDD18SMPS, L7 VDD18SMPS, L8 VSS, L9 VDDCORE, L10 VSS, L11 VDDCORE, L12 VSS, L13 VDD, L14 VSS, L15 VSS, M4 VSS, M5 VDDA18_2, M8 VDDCORE, M9 VSS, M10 VDDCORE, M11 VSS, M12 VDDCORE, M13 VSS, M14 VDD, N5 VSS, N8 VSS, N9 VDDCORE, N10 VSS, N11 VDD, N12 VSS, N13 VDD, N14 VSS, P8 VDD, P9 VSS, P10 VDD, P11 VSS, P12 VDD, P13 VSS, P14 VDD, R9 VDD, R10 VSS, R11 VSS, T6 VREFP, T7 VREFM, T9 VDDA18ADC, T10 VSSA18ADC, T12 VSS, V12 VSS, W1 VSS, W20 VSS, Y2 VSS, Y19 VSS
part B pins: B7 PH0-OSC_IN, C7 PH1-OSC_OUT, E2 PB3, G2 PC14-OSC32_IN, G3 PC15-OSC32_OUT, G4 NRST, H2 BOOT0, N15 PA15, N19 PA13, N20 PA14, Y8 PB4
part C pins: B19 PB7, C18 PB9, C19 PD2, C20 PD3, D17 PE4, D18 PD0, D19 PE6, D20 PE7, E4 PA12, E16 PC11, E17 PF0, E18 PD1, E19 PE9, E20 PE10, F5 PC13, F16 PC10, F17 PF4, F18 PD4, F19 PD13, G17 PF2, G18 PD14, G19 PB8, H15 PC9, H17 PF1, H18 PE8, H19 PE11, H20 PE13, J17 PE5, J18 PD5, J19 PE14, J20 PE15, K16 PD15, K17 PE12, K18 PC0, K19 PC1, L16 PC2, L17 PC3, L18 PF11, L19 PF10, M15 PF13, M16 PF12, M17 PF15, M18 PF14, M19 PE3, M20 PE2, N7 PB15, N18 PA11, P6 PC6, P7 PA4, R2 PA0, R3 PD12, R4 PA1, R5 PC7, R8 PA6, R12 PB6, R13 PC5, T4 PD7, T5 PA3, T8 PB12, T15 PA7, U1 PD6, U2 PB14, U3 PD11, U4 PA5, U5 PD9, U6 PE0, U7 PE1, U8 PB0, U14 PB5, V1 PD10, V3 PA2, V4 PD8, V5 PB2, V6 PF7, V7 PF3, V8 PB11, W2 PB13, W3 PF8, W4 PF6, W7 PC8, W8 PB1, W14 PA8, W16 PA9, W19 PF9, Y3 PF5, Y4 PC12, Y5 PB10, Y13 PC4, Y16 PA10
part D pins: A8 PJ9, A9 PJ11, B2 PM9, B8 PJ10, C1 PM5, C2 PM6, C3 PM8, C8 PJ8, C9 PJ12, D1 PM1, D2 PM2, D3 PM3, D7 PJ7, D8 PJ6, E1 PM11, E3 PM13, E5 PM4, E10 PJ5, E11 PJ2, E12 PO7, F2 PM10, F4 PM14, F6 PM0, F9 PJ4, F10 PJ3, F11 PG6, F12 PO9, G8 PM7, G9 PJ1, G11 PJ0, G12 PO8, H3 PM12, M6 PG14, M7 PG9, N6 PG13, N16 PN1, N17 PN6, P5 PG12, P15 PN2, P16 PN0, P17 PO4, P18 PO0, P19 PN15, R6 PG0, R7 PG1, R14 PI5, R15 PO6, R16 PN10, R17 PN13, R18 PN5, R19 PN14, T1 PG2, T2 PM15, T3 PG10, T14 PG7, T16 PO2, T17 PN9, T18 PO1, T19 PN12, T20 PN11, U13 PI6, U15 PI4, U16 PI1, U17 PO5, U18 PN7, U19 PO3, U20 PN8, V2 PG11, V13 PI12, V14 PI2, V15 PI3, V16 PI0, V17 PI9, V18 PG5, V19 PN3, V20 PN4, W5 PG8, W6 PG15, W13 PI7, W15 PI10, W17 PG4, W18 PG3, Y17 PI11, Y18 PI8
part E pins: A3 OTG1_HSDP, A4 OTG2_TXRTUNE, A5 OTG2_HSDM, A12 PQ12, A13 PQ2, A16 PP10, A17 PP2, A18 PP3, B3 OTG1_HSDM, B4 OTG1_TXRTUNE, B5 OTG2_HSDP, B6 UCPD2_CC1, B9 PR5, B10 PQ8, B11 PQ6, B12 PQ11, B13 PQ4, B14 PR3, B15 PQ10, B16 PP11, B17 PP5, B18 PP6, C4 OTG1_ID, C5 OTG2_ID, C6 UCPD2_CC2, C10 PQ1, C11 PQ7, C12 PQ13, C13 PQ3, C14 PR0, C15 PR1, C16 PP8, C17 PP9, D4 OTG1_VBUS, D5 OTG2_VBUS, D6 UCPD1_CC1, D9 PQ9, D10 PQ15, D11 PQ0, D12 PQ5, D13 PR4, D14 PR2, D15 PP1, D16 PP7, E6 UCPD1_CC2, E13 PQ14, E14 PP0, E15 PP12, F15 PP4, M1 LVDS1_D0P, M2 LVDS1_D0N, M3 LVDS1_D1N, N1 LVDS1_D2N, N2 LVDS1_D2P, N3 LVDS1_D4N, N4 LVDS1_D1P, P2 LVDS1_D3N, P3 LVDS1_D3P, P4 LVDS1_D4P
part F pins: T11 VDDA18CSIDSI, T13 VDDA08CSIDSI, U9 DSI_CKP, U10 DSI_CKN, U11 CSI_D1P, U12 CSI_D1N, V9 CSI_REXT_DSI_REXT, V10 DSI_D1N, V11 CSI_CKP, W9 DSI_D0P, W10 DSI_D1P, W11 CSI_CKN, W12 CSI_D0P, Y9 DSI_D0N, Y12 CSI_D0N
1 alternate drawing of the same symbol

## IC_STM32WBA22CEU6
designator U?
part A pins: 1 PB12, 2 NC, 3 PA8, 4 PA7, 5 PA6, 7 PA5, 8 NC, 9 NC, 10 PA2, 12 PA1, 13 PA0, 14 PB9, 15 PB8, 16 PC15-OSC32_OUT, 17 PC14-OSC32_IN, 18 PC13, 19 NC, 20 PB6, 21 PB5, 23 PB4, 24 PB3, 25 PA15, 26 PA14-SWCLK, 27 PA13-SWDIO, 28 PA12, 29 PA11, 30 PB2, 31 NC, 32 NC, 33 PB15, 34 PH3-BOOT0, 36 NRST, 40 OSC_OUT, 41 OSC_IN, 45 PA10, 46 PA9, 47 NC, 48 NC
part B pins: 6 VDDA, 11 VDD, 22 VDD, 35 VDD, 43 VDD, 44 VCAP, 49 VSS(ExPAD)
part C pins: 37 RF, 38 VDDHPA, 39 VDDRF, 42 VDDRFPA

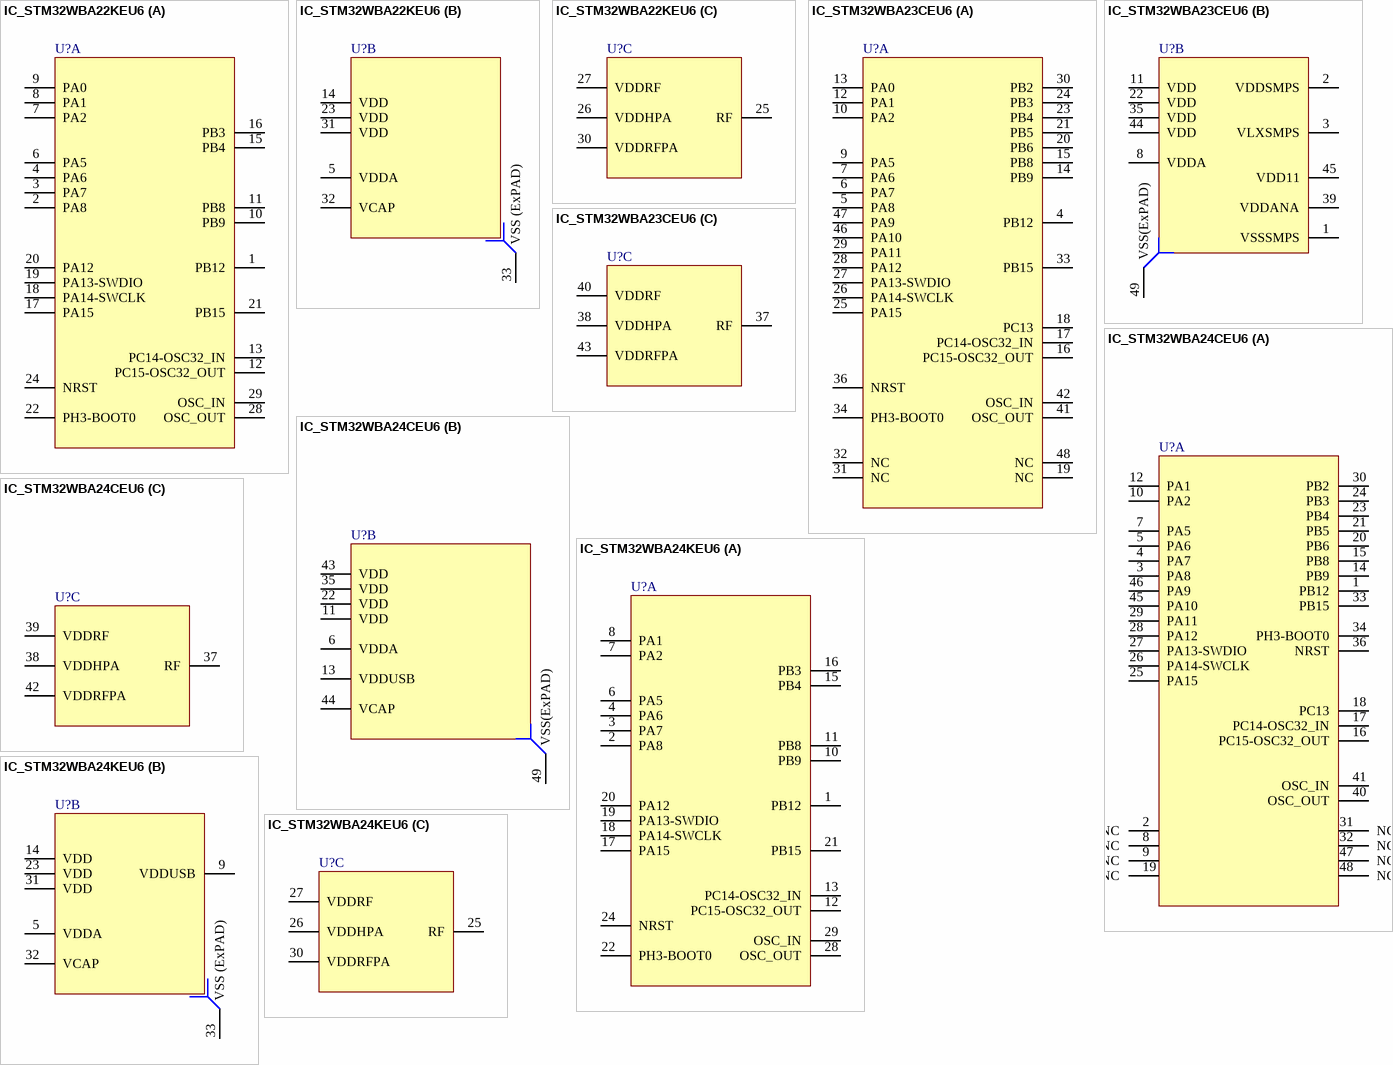
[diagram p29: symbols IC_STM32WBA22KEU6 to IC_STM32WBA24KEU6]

## IC_STM32WBA22KEU6
designator U?
part A pins: 1 PB12, 2 PA8, 3 PA7, 4 PA6, 6 PA5, 7 PA2, 8 PA1, 9 PA0, 10 PB9, 11 PB8, 12 PC15-OSC32_OUT, 13 PC14-OSC32_IN, 15 PB4, 16 PB3, 17 PA15, 18 PA14-SWCLK, 19 PA13-SWDIO, 20 PA12, 21 PB15, 22 PH3-BOOT0, 24 NRST, 28 OSC_OUT, 29 OSC_IN
part B pins: 5 VDDA, 14 VDD, 23 VDD, 31 VDD, 32 VCAP, 33 VSS (ExPAD)
part C pins: 25 RF, 26 VDDHPA, 27 VDDRF, 30 VDDRFPA

## IC_STM32WBA23CEU6
designator U?
part A pins: 4 PB12, 5 PA8, 6 PA7, 7 PA6, 9 PA5, 10 PA2, 12 PA1, 13 PA0, 14 PB9, 15 PB8, 16 PC15-OSC32_OUT, 17 PC14-OSC32_IN, 18 PC13, 19 NC, 20 PB6, 21 PB5, 23 PB4, 24 PB3, 25 PA15, 26 PA14-SWCLK, 27 PA13-SWDIO, 28 PA12, 29 PA11, 30 PB2, 31 NC, 32 NC, 33 PB15, 34 PH3-BOOT0, 36 NRST, 41 OSC_OUT, 42 OSC_IN, 46 PA10, 47 PA9, 48 NC
part B pins: 1 VSSSMPS, 2 VDDSMPS, 3 VLXSMPS, 8 VDDA, 11 VDD, 22 VDD, 35 VDD, 39 VDDANA, 44 VDD, 45 VDD11, 49 VSS(ExPAD)
part C pins: 37 RF, 38 VDDHPA, 40 VDDRF, 43 VDDRFPA

## IC_STM32WBA24CEU6
designator U?
part A pins: 1 PB12, 2 NC, 3 PA8, 4 PA7, 5 PA6, 7 PA5, 8 NC, 9 NC, 10 PA2, 12 PA1, 14 PB9, 15 PB8, 16 PC15-OSC32_OUT, 17 PC14-OSC32_IN, 18 PC13, 19 NC, 20 PB6, 21 PB5, 23 PB4, 24 PB3, 25 PA15, 26 PA14-SWCLK, 27 PA13-SWDIO, 28 PA12, 29 PA11, 30 PB2, 31 NC, 32 NC, 33 PB15, 34 PH3-BOOT0, 36 NRST, 40 OSC_OUT, 41 OSC_IN, 45 PA10, 46 PA9, 47 NC, 48 NC
part B pins: 6 VDDA, 11 VDD, 13 VDDUSB, 22 VDD, 35 VDD, 43 VDD, 44 VCAP, 49 VSS(ExPAD)
part C pins: 37 RF, 38 VDDHPA, 39 VDDRF, 42 VDDRFPA

## IC_STM32WBA24KEU6
designator U?
part A pins: 1 PB12, 2 PA8, 3 PA7, 4 PA6, 6 PA5, 7 PA2, 8 PA1, 10 PB9, 11 PB8, 12 PC15-OSC32_OUT, 13 PC14-OSC32_IN, 15 PB4, 16 PB3, 17 PA15, 18 PA14-SWCLK, 19 PA13-SWDIO, 20 PA12, 21 PB15, 22 PH3-BOOT0, 24 NRST, 28 OSC_OUT, 29 OSC_IN
part B pins: 5 VDDA, 9 VDDUSB, 14 VDD, 23 VDD, 31 VDD, 32 VCAP, 33 VSS (ExPAD)
part C pins: 25 RF, 26 VDDHPA, 27 VDDRF, 30 VDDRFPA

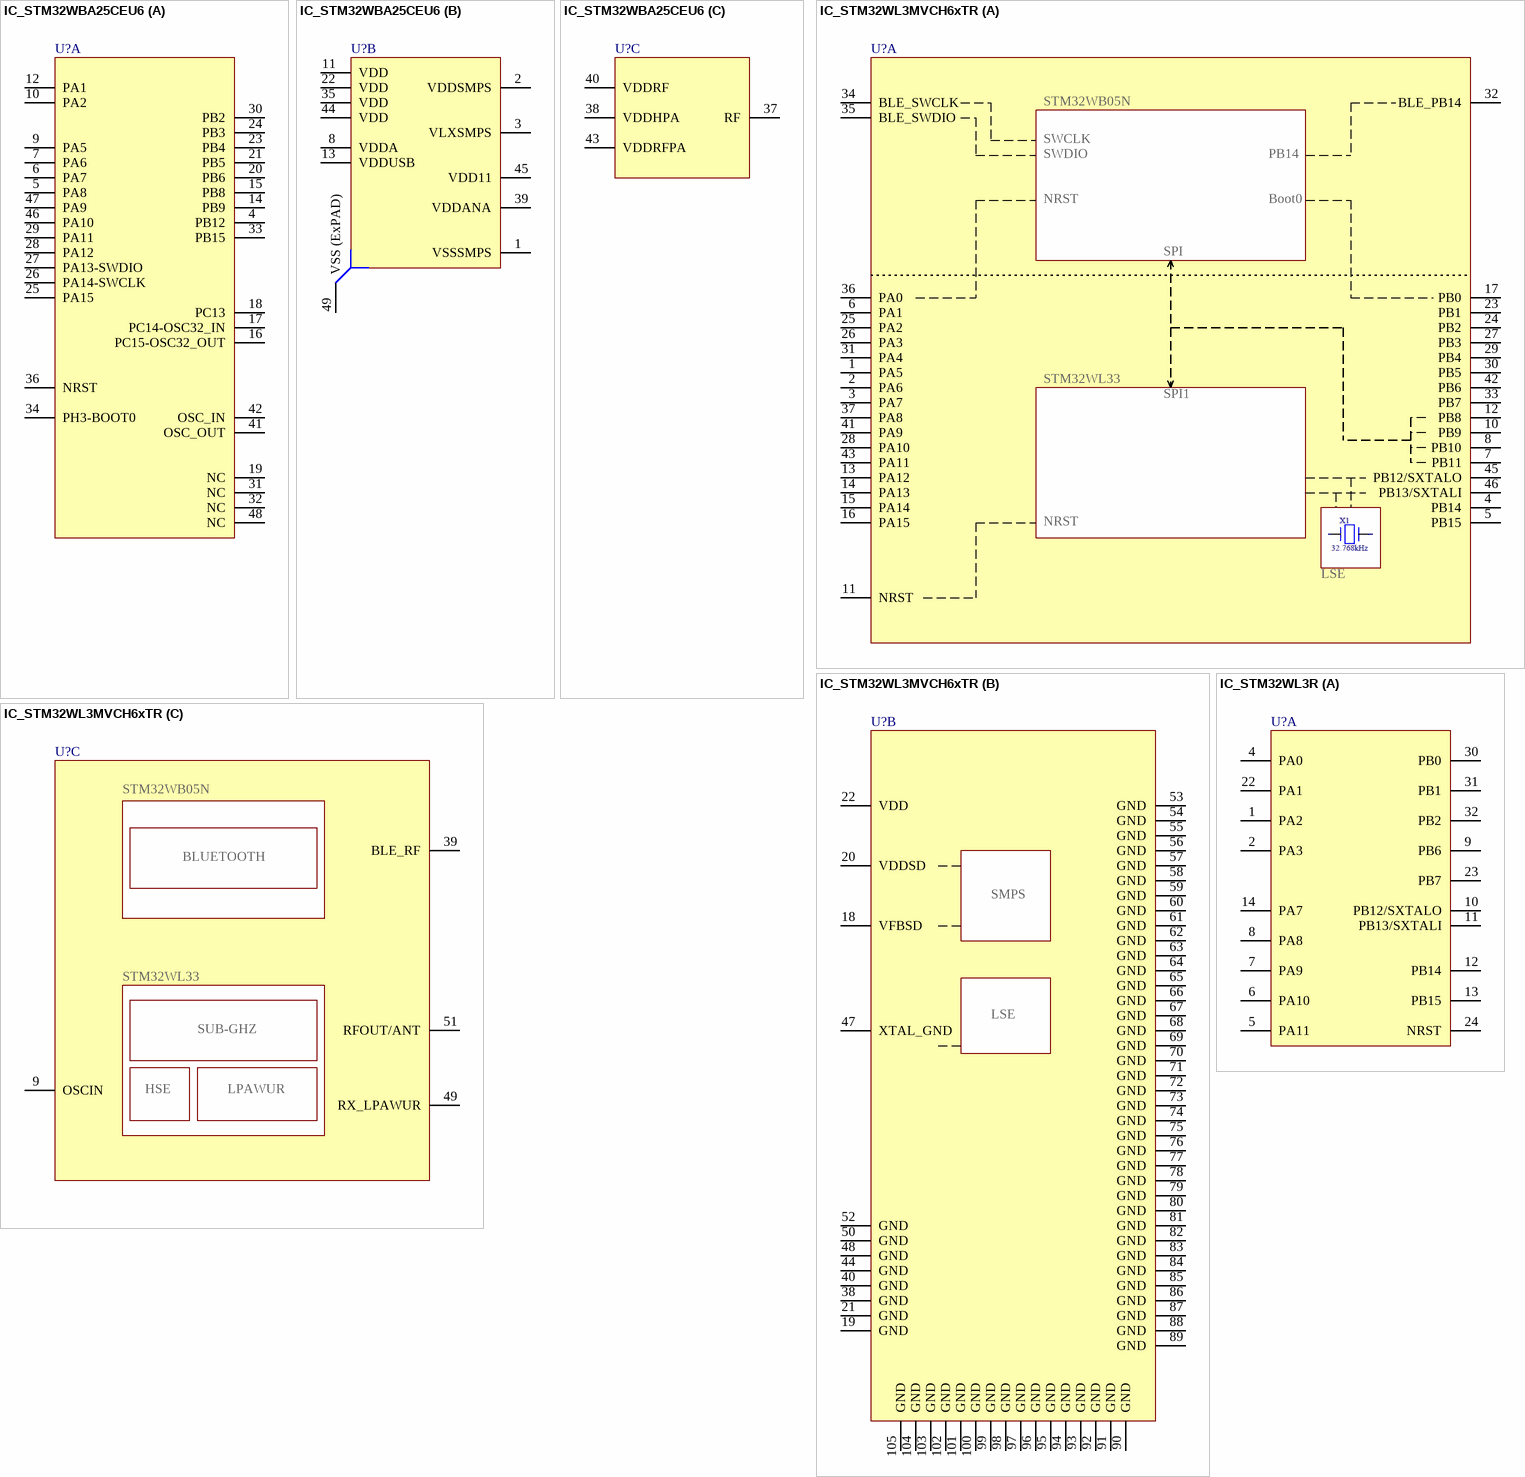
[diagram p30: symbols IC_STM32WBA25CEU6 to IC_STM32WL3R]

## IC_STM32WBA25CEU6
designator U?
part A pins: 4 PB12, 5 PA8, 6 PA7, 7 PA6, 9 PA5, 10 PA2, 12 PA1, 14 PB9, 15 PB8, 16 PC15-OSC32_OUT, 17 PC14-OSC32_IN, 18 PC13, 19 NC, 20 PB6, 21 PB5, 23 PB4, 24 PB3, 25 PA15, 26 PA14-SWCLK, 27 PA13-SWDIO, 28 PA12, 29 PA11, 30 PB2, 31 NC, 32 NC, 33 PB15, 34 PH3-BOOT0, 36 NRST, 41 OSC_OUT, 42 OSC_IN, 46 PA10, 47 PA9, 48 NC
part B pins: 1 VSSSMPS, 2 VDDSMPS, 3 VLXSMPS, 8 VDDA, 11 VDD, 13 VDDUSB, 22 VDD, 35 VDD, 39 VDDANA, 44 VDD, 45 VDD11, 49 VSS (ExPAD)
part C pins: 37 RF, 38 VDDHPA, 40 VDDRF, 43 VDDRFPA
